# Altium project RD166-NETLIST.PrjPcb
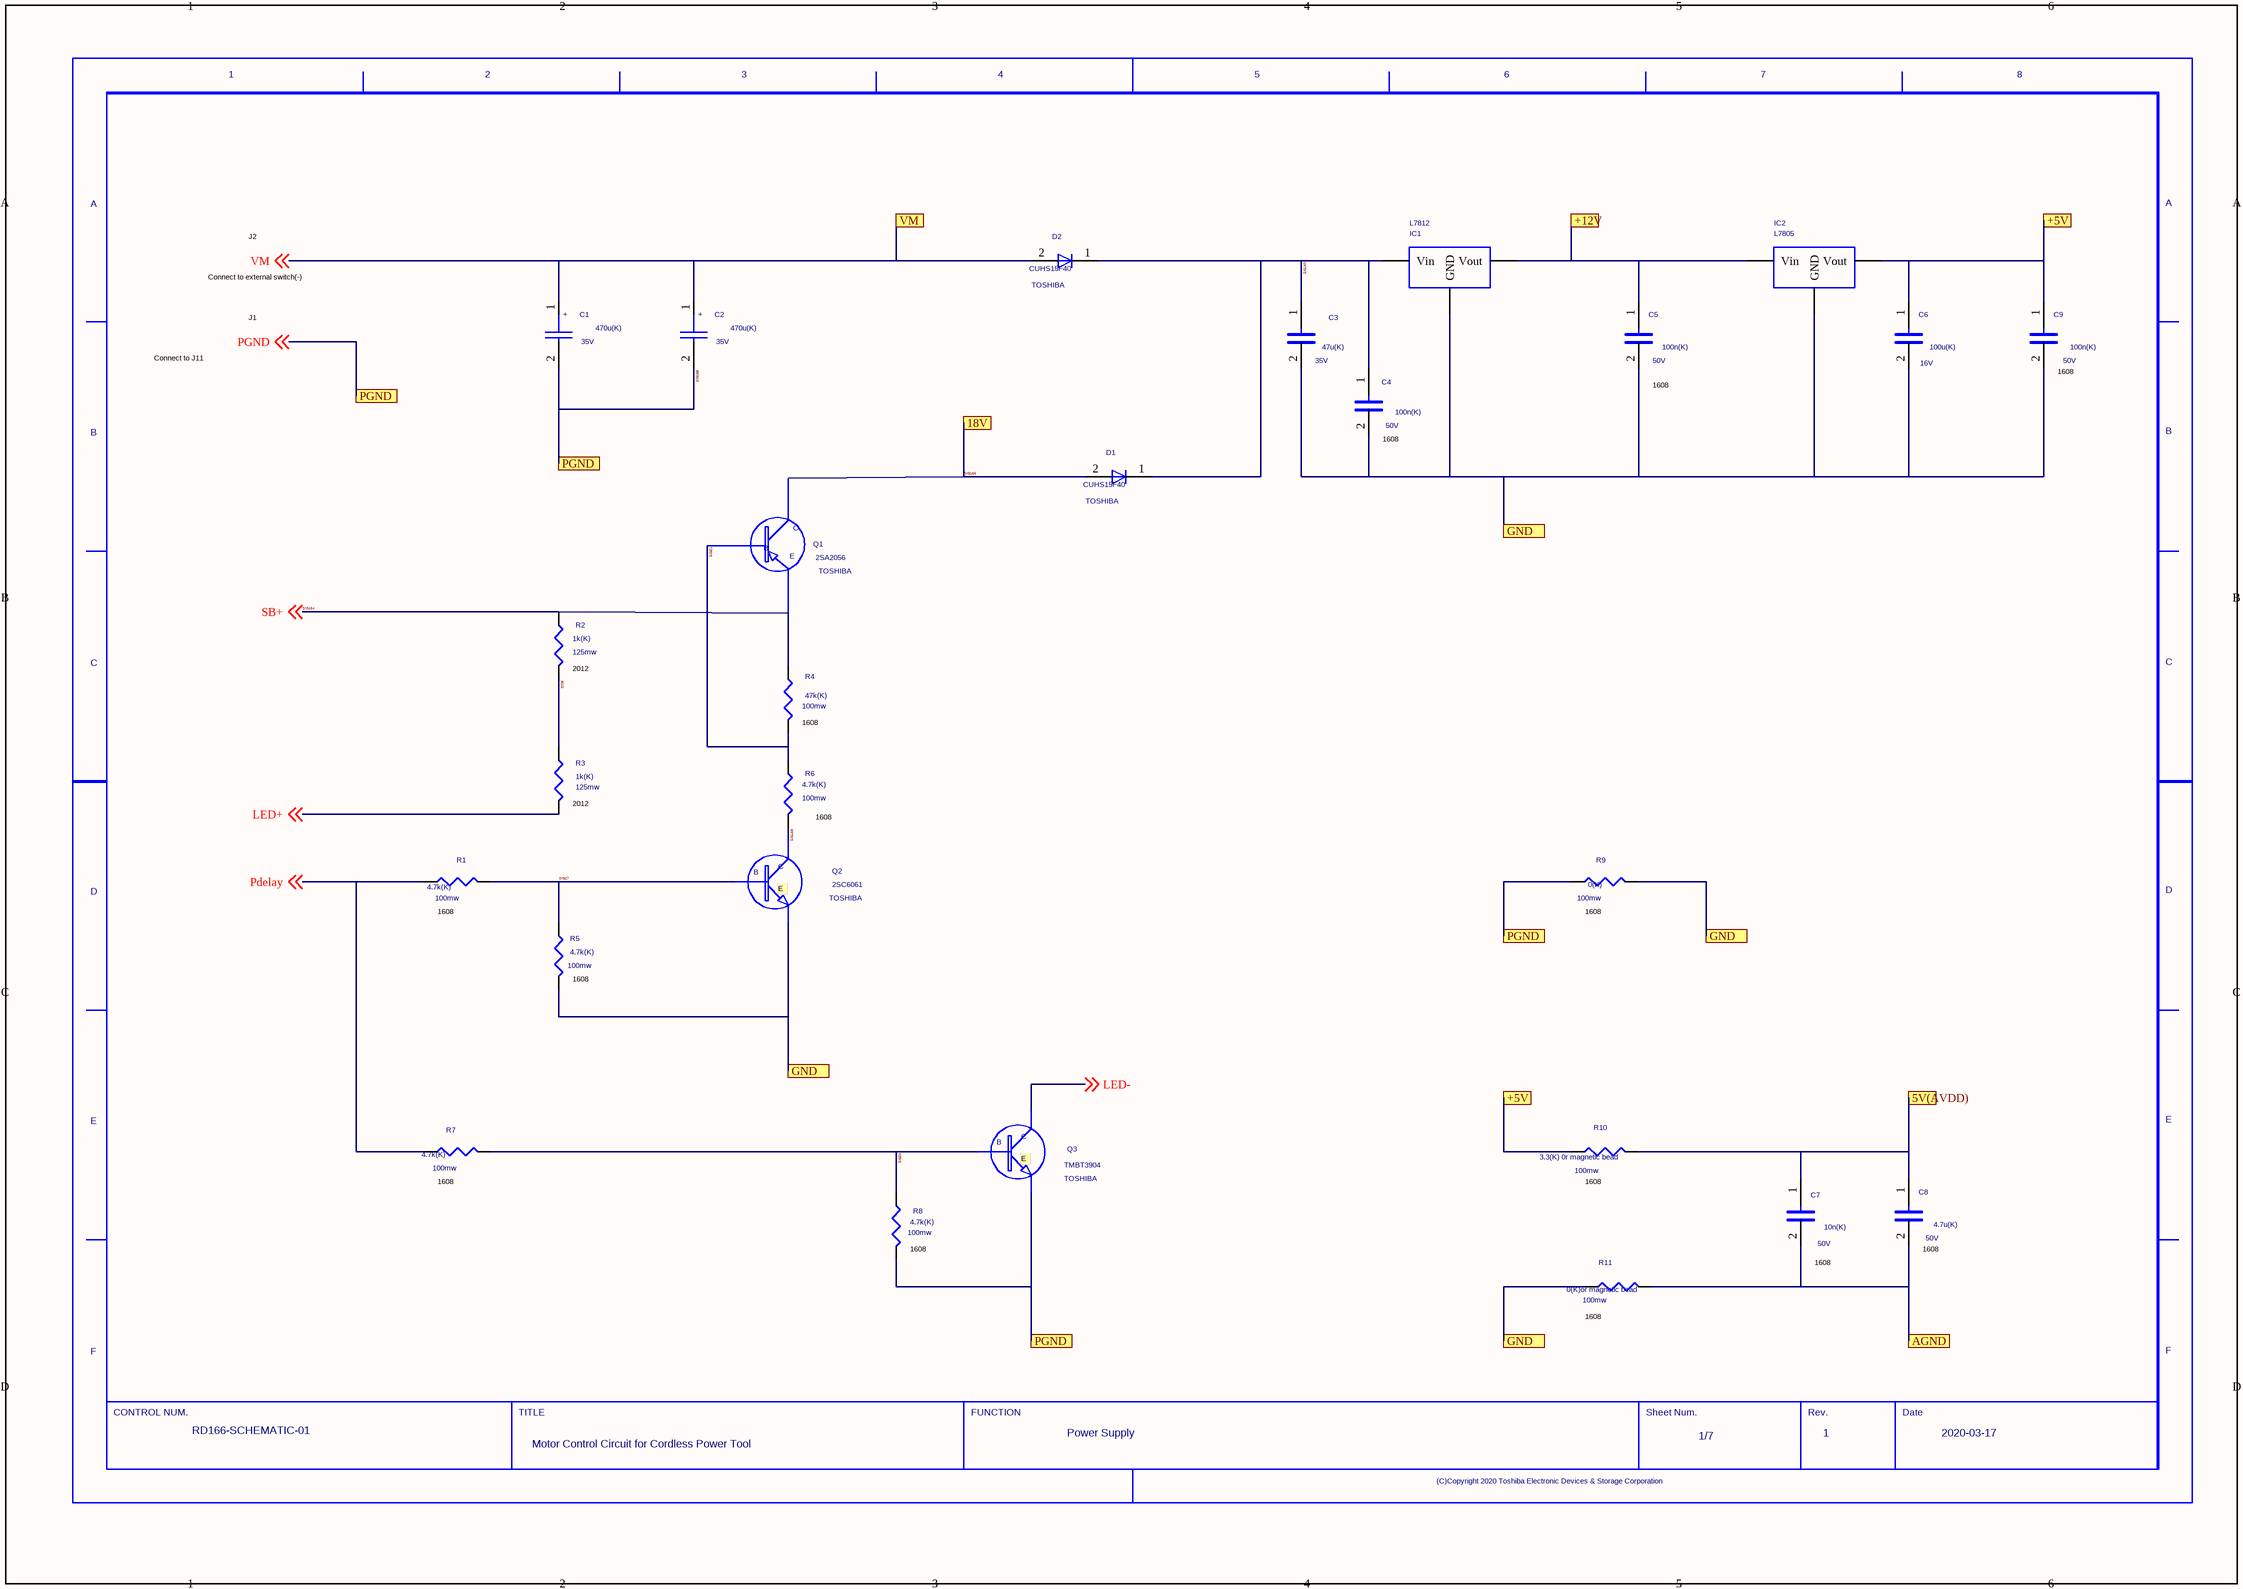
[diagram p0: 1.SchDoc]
7 sheets, 145 parts. Net scope: flat (ports and power ports of the same name join across sheets).
Sheets:
  1.SchDoc
  2.SchDoc
  3.SchDoc
  4.SchDoc
  5.SchDoc
  6.SchDoc
  7.SchDoc

## Sheet 1.SchDoc
size 420 x 297 mm

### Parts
(Parts that share a designator on the sheet are numbered #1, #2 ... from top to bottom, then left to right.)
C1  VAL2: 35V  VAL1: 470u(K)  (hidden comment: CP)
C2  VAL2: 35V  VAL1: 470u(K)  (hidden comment: CP)
C3  VAL2: 35V  VAL1: 47u(K)  (hidden comment: C)
C4  VAL2: 50V  VAL1: 100n(K)  (hidden comment: C)
C5  VAL2: 50V  VAL1: 100n(K)  (hidden comment: C)
C6  VAL2: 16V  VAL1: 100u(K)  (hidden comment: C)
C7  VAL2: 50V  VAL1: 10n(K)  (hidden comment: C)
C8  VAL2: 50V  VAL1: 4.7u(K)  (hidden comment: C)
C9  VAL2: 50V  VAL1: 100n(K)  (hidden comment: C)
D1  USERCOMPTEXT3: TOSHIBA  VAL3: CUHS15F40  (hidden comment: D)
D2  USERCOMPTEXT3: TOSHIBA  VAL3: CUHS15F40  (hidden comment: D)
IC1  VAL3: L7812  (hidden comment: L7805)
IC2  L7805
Q1  USERCOMPTEXT3: TOSHIBA  VAL3: 2SA2056  (hidden comment: PNP_2)
Q2  USERCOMPTEXT3: TOSHIBA  VAL3: 2SC6061  (hidden comment: NPN)
Q3  USERCOMPTEXT3: TOSHIBA  VAL3: TMBT3904  (hidden comment: NPN)
R1  VAL2: 100mw  VAL1: 4.7k(K)  (hidden comment: RES_SMD__2)
R2  VAL2: 125mw  VAL1: 1k(K)  (hidden comment: RES_SMD__2)
R3  VAL2: 125mw  VAL1: 1k(K)  (hidden comment: RES_SMD__2)
R4  VAL2: 100mw  VAL1: 47k(K)  (hidden comment: RES_SMD__2)
R5  VAL2: 100mw  VAL1: 4.7k(K)  (hidden comment: RES_SMD__2)
R6  VAL2: 100mw  VAL1: 4.7k(K)  (hidden comment: RES_SMD__2)
R7  VAL2: 100mw  VAL1: 4.7k(K)  (hidden comment: RES_SMD__2)
R8  VAL2: 100mw  VAL1: 4.7k(K)  (hidden comment: RES_SMD__2)
R9  VAL2: 100mw  VAL1: 0(K)  (hidden comment: RES_SMD__2)
R10  VAL2: 100mw  VAL1: 3.3(K) 0r magnetic bead  (hidden comment: RES_SMD__2)
R11  VAL2: 100mw  VAL1: 0(K)or magnetic bead  (hidden comment: RES_SMD__2)
U?#1  DATE: 2020-03-17  REVISION: 1  SHEETNUMBER: 1/7  FUNCTION: Power Supply  DRAWINGNUMBER: RD166-SCHEMATIC-01  TITLE: Motor Control Circuit for / Cordless Power Tool  (hidden comment: WAKU_DEF100)

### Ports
5V(AVDD), 18V, +5V, +12V, AGND, GND, PGND, VM

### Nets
LED+: R3.2 ; off-sheet LED+
LED-: Q3.3 ; off-sheet LED-
Pdelay: R1.2 R7.1 ; off-sheet Pdelay
SIG8: R2.2 R3.1
SIG21: Q1.1 R4.1 R6.1
SIG24: Q3.1 R7.2 R8.1
SIG27: Q2.1 R1.1 R5.2
SIG29: C3.2 C4.2 C5.2 C6.2 C9.2 IC1.2(GND) IC2.2(GND) Q2.2 R5.1 R9.2 R11.1 ; port GND
SIG42: C6.1 C9.1 IC2.3(Vout) R10.1 ; port +5V
SIG163: C3.1 C4.1 D1.1(C) D2.1(C) IC1.1(Vin)
SIG164: Q1.2 R2.1 R4.2 ; off-sheet SB+  [also labelled SB+]
SIG165: C1.2 C2.2 Q3.2 R8.2 R9.1 ; off-sheet PGND, port PGND  [also labelled PGND]
SIG166: D1.2(A) Q1.3 ; port 18V
SIG169: Q2.3 R6.2
VM: C1.1 C2.1 D2.2(A) ; off-sheet VM, port VM
NetC5_1: C5.1 IC1.3(Vout) IC2.1(Vin) ; port +12V
NetC7_1: C7.1 C8.1 R10.2 ; port 5V(AVDD)
NetC7_2: C7.2 C8.2 R11.2 ; port AGND

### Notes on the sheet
- J2
- Connect to external switch(-)
- J1
- Connect to J11
- (near C5) 1608
- (near C9) 1608
- (near C4) 1608
- (near R2) 2012
- (near R4) 1608
- (near R3) 2012
- 1608
- (near R1) 1608
- (near R9) 1608
- (near R5) 1608
- (near R7) 1608
- (near R10) 1608
- (near R8) 1608
- (near C7) 1608
- (near C8) 1608
- (near R11) 1608

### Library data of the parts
C1 C2 = CP: PARTNAME: 470UF_K; OriginalSymbolOrigin: (2540,10160); UPDATETIME: 16:13:42; UPDATEUSER: fukuda-y; TIME: 15:02:55; SAVECOUNT: 52; SAVEAREA0: -1450,-153,20294,13055
C3 = C: PARTNAME: 47UF_K; OriginalSymbolOrigin: (2540,7620)
C4 C5 C9 = C: PARTNAME: 100NF_K; OriginalSymbolOrigin: (2540,7620)
C6 = C: PARTNAME: 100UF_K; OriginalSymbolOrigin: (2540,7620)
C7 = C: PARTNAME: 10NF_K; OriginalSymbolOrigin: (2540,7620)
C8 = C: PARTNAME: 4-7UF_K; OriginalSymbolOrigin: (2540,7620)
D1 D2 = D: OriginalSymbolOrigin: (5080,5080); UPDATETIME: 14:20:16; UPDATEUSER: 19870035; TIME: 14:49:55; SAVECOUNT: 3; SAVEAREA0: -225,-91,12804,7836
IC1 IC2 = L7805: OriginalSymbolOrigin: (0,0); SAVEAREA0: -9544,-9544,24191,4569; SAVECOUNT: 2; UPDATETIME: 10:58:54; UPDATEUSER: t5459927; TIME: 14:48:25
Q1 = PNP_2: OriginalSymbolOrigin: (-10142,10288); SAVEAREA0: -33169,-19071,44577,13455; SAVECOUNT: 4; UPDATETIME: 08:35:52; UPDATEUSER: t5459927; TIME: 14:48:25
Q2 Q3 = NPN: OriginalSymbolOrigin: (-2537,2540); SAVEAREA0: -26556,-14535,34190,10878; SAVECOUNT: 4; UPDATETIME: 08:38:55; UPDATEUSER: t5459927; TIME: 14:48:25
R1 R5 = RES_SMD__2: PARTNAME: 4-7K_K; OriginalSymbolOrigin: (2552,2560); SAVEAREA0: -3866,-5393,16243,5158; SAVECOUNT: 2; UPDATETIME: 10:20:03; UPDATEUSER: t5459927; TIME: 14:48:25
R2 R3 = RES_SMD__2#1: PARTNAME: 1K_K; OriginalSymbolOrigin: (2552,2560); SAVEAREA0: -3866,-5393,16243,5158; SAVECOUNT: 2; UPDATETIME: 10:20:03; UPDATEUSER: t5459927; TIME: 14:48:25; CaptureCellPackProp: RES_SMD__2##1
R4 = RES_SMD__2: PARTNAME: 47K_K; OriginalSymbolOrigin: (2552,2560); SAVEAREA0: -3866,-5393,16243,5158; SAVECOUNT: 2; UPDATETIME: 10:20:03; UPDATEUSER: t5459927; TIME: 14:48:25
R6-R8 = RES_SMD__2#1: PARTNAME: 4-7K_K; OriginalSymbolOrigin: (2552,2560); SAVEAREA0: -3866,-5393,16243,5158; SAVECOUNT: 2; UPDATETIME: 10:20:03; UPDATEUSER: t5459927; TIME: 14:48:25; CaptureCellPackProp: RES_SMD__2##1
R9 = RES_SMD__2#1: PARTNAME: 0_K; OriginalSymbolOrigin: (2552,2560); SAVEAREA0: -3866,-5393,16243,5158; SAVECOUNT: 2; UPDATETIME: 10:20:03; UPDATEUSER: t5459927; TIME: 14:48:25; CaptureCellPackProp: RES_SMD__2##1
R10 = RES_SMD__2#1: PARTNAME: 3-3_K_OR_MAGNETIC_BEAD; OriginalSymbolOrigin: (2552,2560); SAVEAREA0: -3866,-5393,16243,5158; SAVECOUNT: 2; UPDATETIME: 10:20:03; UPDATEUSER: t5459927; TIME: 14:48:25; CaptureCellPackProp: RES_SMD__2##1
R11 = RES_SMD__2#1: PARTNAME: 0_K_OR_MAGNETIC_BEAD; OriginalSymbolOrigin: (2552,2560); SAVEAREA0: -3866,-5393,16243,5158; SAVECOUNT: 2; UPDATETIME: 10:20:03; UPDATEUSER: t5459927; TIME: 14:48:25; CaptureCellPackProp: RES_SMD__2##1
U?#1 = WAKU_DEF100: OriginalSymbolOrigin: (10160,284480); SAVECOUNT: 4; UPDATETIME: 15:05:57; UPDATEUSER: t5459927; TIME: 14:30:25; SAVEAREA0: 198008,-65938,436964,90161; PLOTTIME: HH:MM

## Sheet 2.SchDoc
size 420 x 297 mm
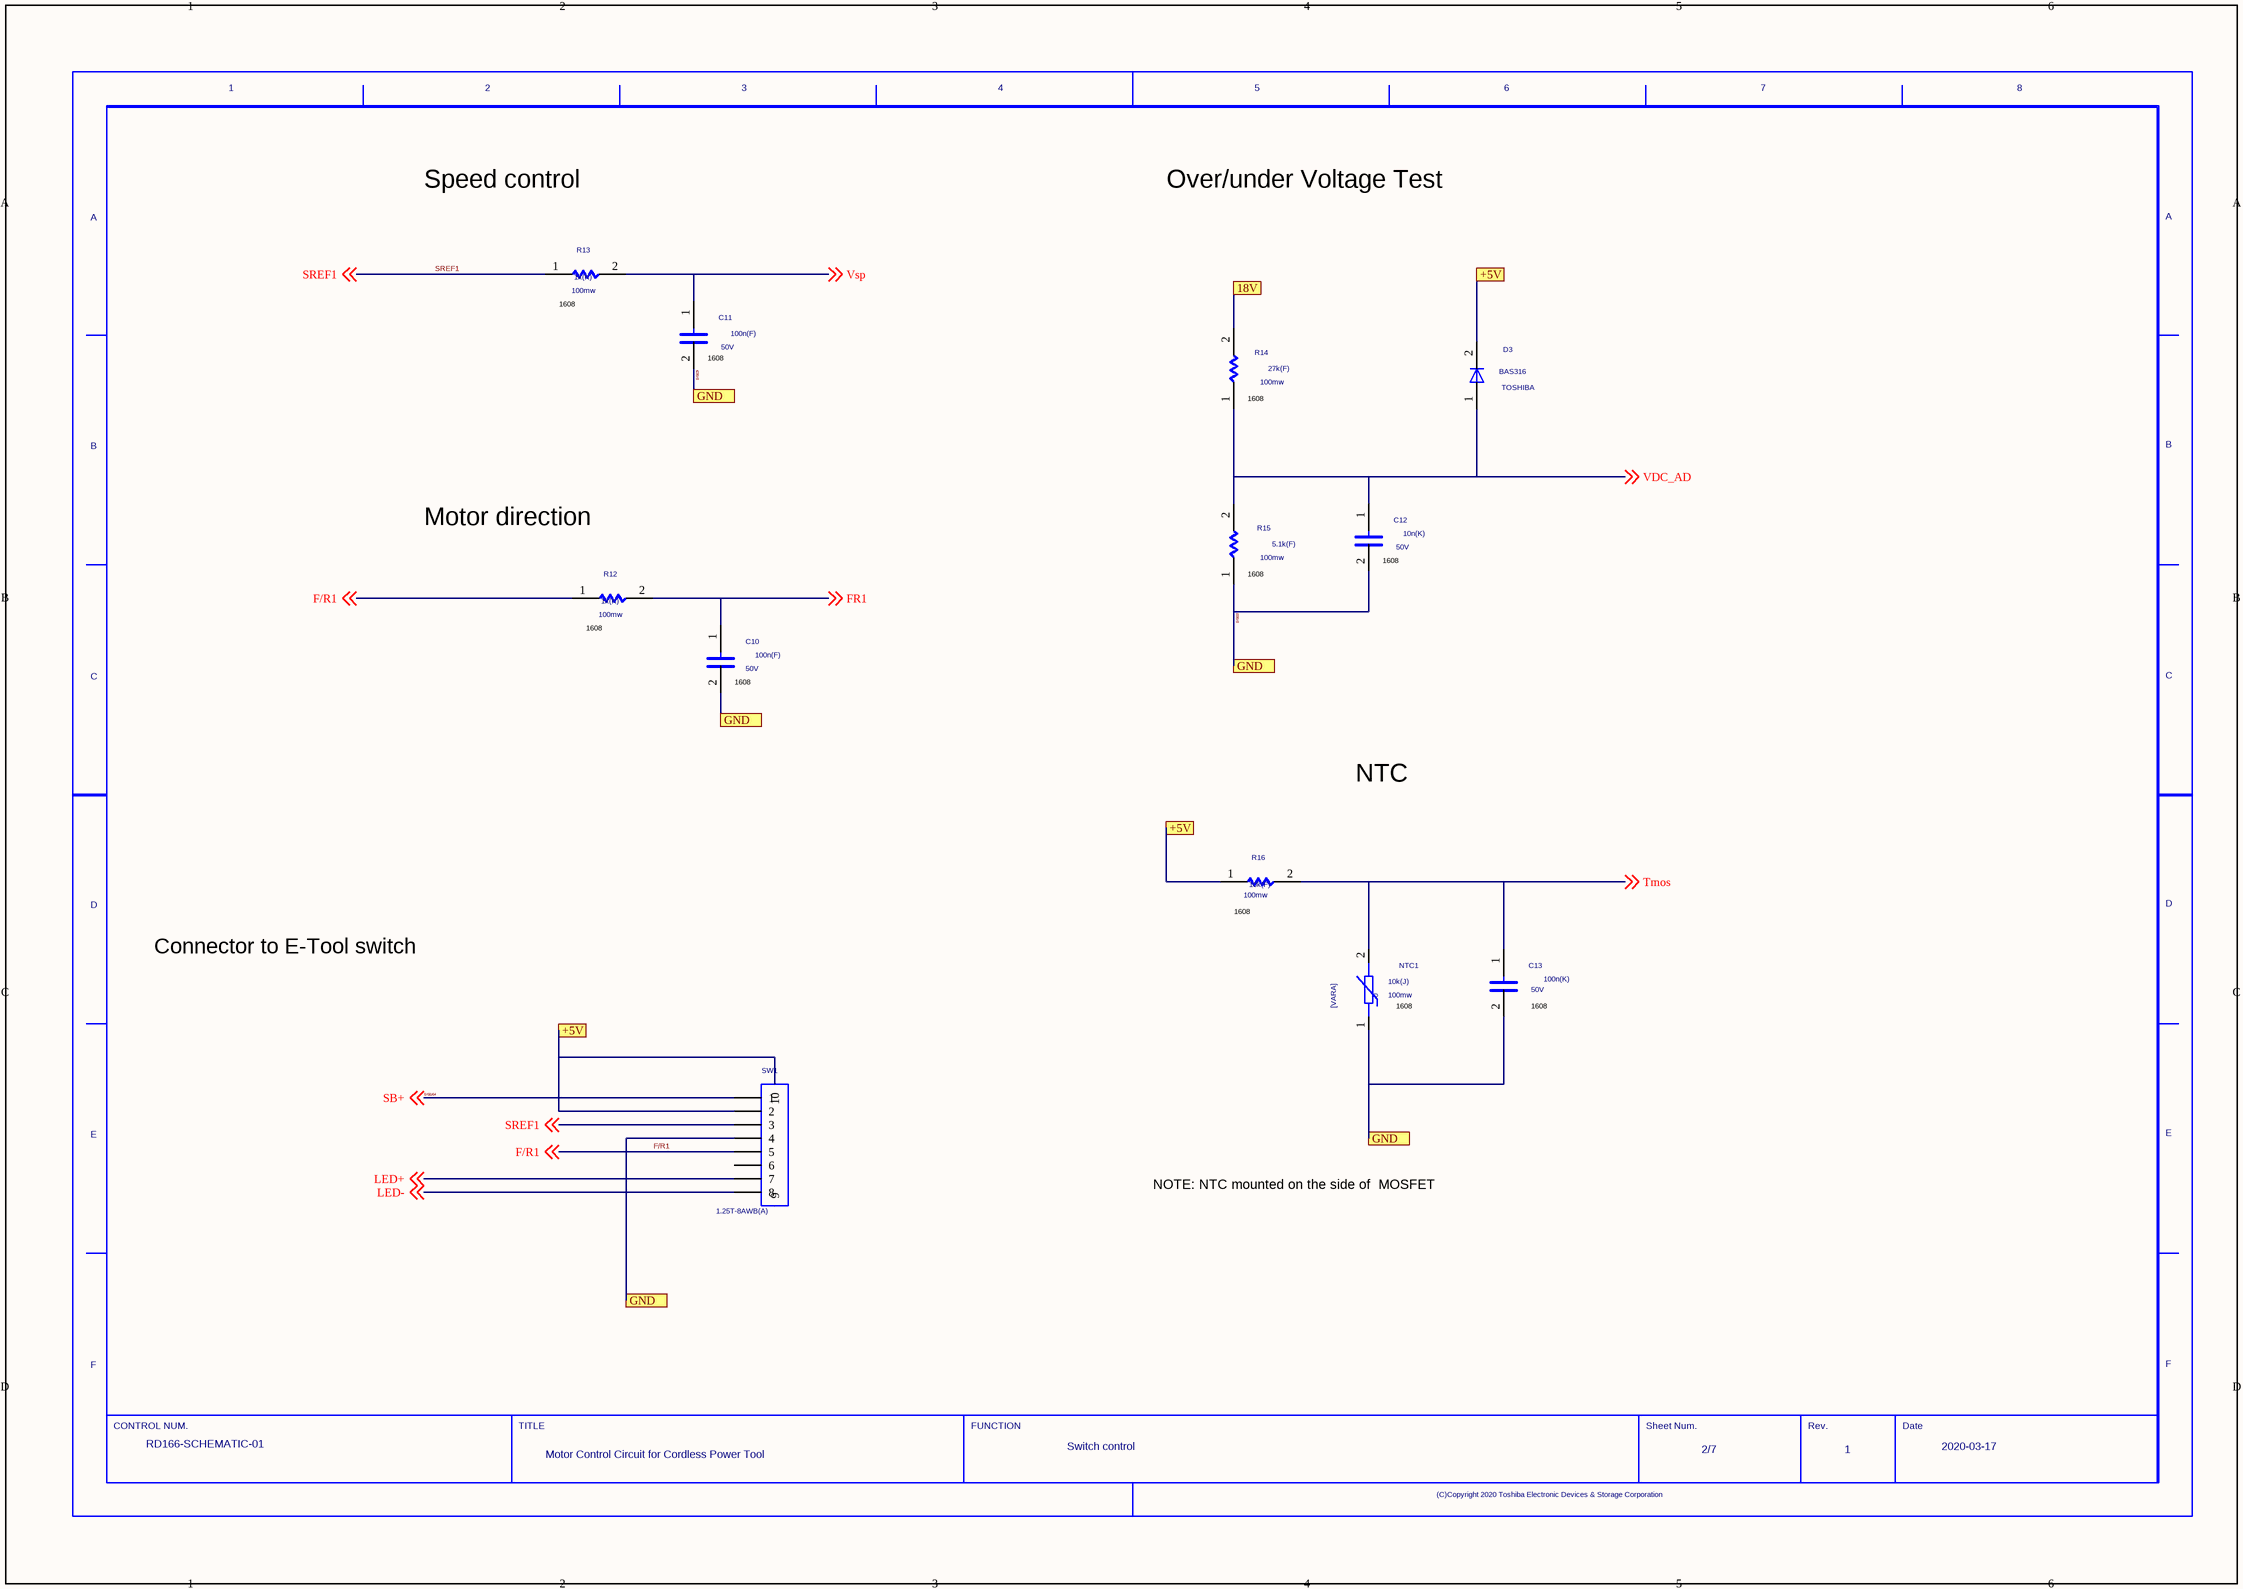
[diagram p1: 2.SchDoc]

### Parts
(Parts that share a designator on the sheet are numbered #1, #2 ... from top to bottom, then left to right.)
C10  VAL2: 50V  VAL1: 100n(F)  (hidden comment: C)
C11  VAL2: 50V  VAL1: 100n(F)  (hidden comment: C)
C12  VAL2: 50V  VAL1: 10n(K)  (hidden comment: C)
C13  VAL2: 50V  VAL1: 100n(K)  (hidden comment: C)
D3  USERCOMPTEXT3: TOSHIBA  VAL3: BAS316  (hidden comment: D)
NTC1  VAL2: 100mw  VAL1: 10k(J)  (hidden comment: VARA)
R12  VAL2: 100mw  VAL1: 1k(K)  (hidden comment: R)
R13  VAL2: 100mw  VAL1: 1k(K)  (hidden comment: R)
R14  VAL2: 100mw  VAL1: 27k(F)  (hidden comment: R)
R15  VAL2: 100mw  VAL1: 5.1k(F)  (hidden comment: R)
R16  VAL2: 100mw  VAL1: 10k(F)  (hidden comment: R)
SW1  VAL3: 1.25T-8AWB(A)  (hidden comment: CON8)
U?#2  DATE: 2020-03-17  REVISION: 1  SHEETNUMBER: 2/7  FUNCTION: Switch control  TITLE: Motor Control Circuit for / Cordless Power Tool  DRAWINGNUMBER: RD166-SCHEMATIC-01  (hidden comment: WAKU_DEF100)

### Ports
18V, +5V, GND

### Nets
F/R1: R12.1 SW1.5 ; off-sheet F/R1
FR1: C10.1 R12.2 ; off-sheet FR1
LED+: SW1.7 ; off-sheet LED+
LED-: SW1.8 ; off-sheet LED-
SIG29: C10.2 C11.2 C12.2 C13.2 NTC1.1 R15.1 SW1.4 ; port GND  [also labelled SIG33]
SIG42: D3.2(C) R16.1 SW1.0(10) SW1.2 ; port +5V
SIG164: SW1.1 ; off-sheet SB+  [also labelled SB+]
SIG166: R14.2 ; port 18V
SREF1: R13.1 SW1.3 ; off-sheet SREF1
Tmos: C13.1 NTC1.2 R16.2 ; off-sheet Tmos
VDC_AD: C12.1 D3.1(A) R14.1 R15.2 ; off-sheet VDC_AD
Vsp: C11.1 R13.2 ; off-sheet Vsp

Not connected (* = marked no-connect by the designer): SW1 6 9

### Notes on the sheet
- Speed control
- Over/under Voltage Test
- (near R13) 1608
- (near C11) 1608
- (near R14) 1608
- Motor direction
- (near R15) 1608
- (near C12) 1608
- (near R12) 1608
- (near C10) 1608
- NTC
- (near R16) 1608
- Connector to E-Tool switch
- (near NTC1) 1608
- (near C13) 1608
- NOTE: NTC mounted on the side of  MOSFET

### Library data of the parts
C10 C11 C13 = C: as C4 on sheet 1
C12 = C: as C7 on sheet 1
D3 = D#1: OriginalSymbolOrigin: (5080,5080); UPDATETIME: 14:20:16; UPDATEUSER: 19870035; TIME: 14:49:55; SAVECOUNT: 3; SAVEAREA0: -225,-91,12804,7836; CaptureCellPackProp: D##1
NTC1 = VARA: PARTNAME: 10K_B3380; OriginalSymbolOrigin: (2540,5080); UPDATETIME: 09:56:50; UPDATEUSER: tomizawa-y; SAVECOUNT: 12; SAVEAREA0: -9950,-8554,25168,13619
R12 R13 = R: PARTNAME: 1K_K; OriginalSymbolOrigin: (5080,5080)
R14 = R#1: PARTNAME: 27K_F; OriginalSymbolOrigin: (5080,5080); CaptureCellPackProp: R##1
R15 = R#1: PARTNAME: 5-1K_F; OriginalSymbolOrigin: (5080,5080); CaptureCellPackProp: R##1
R16 = R: PARTNAME: 10K_F; OriginalSymbolOrigin: (5080,5080)
SW1 = CON8: PARTNAME: 1-25-A; OriginalSymbolOrigin: (0,0); SAVEAREA0: -35474,-32561,34839,4331; SAVECOUNT: 3; UPDATETIME: 16:40:52; UPDATEUSER: t5459927; TIME: 14:48:25
U?#2 = WAKU_DEF100: OriginalSymbolOrigin: (10160,284480); SAVECOUNT: 4; UPDATETIME: 15:06:18; UPDATEUSER: t5459927; TIME: 14:30:25; SAVEAREA0: 198008,-65938,436964,90161; PLOTTIME: HH:MM

## Sheet 3.SchDoc
size 420 x 297 mm
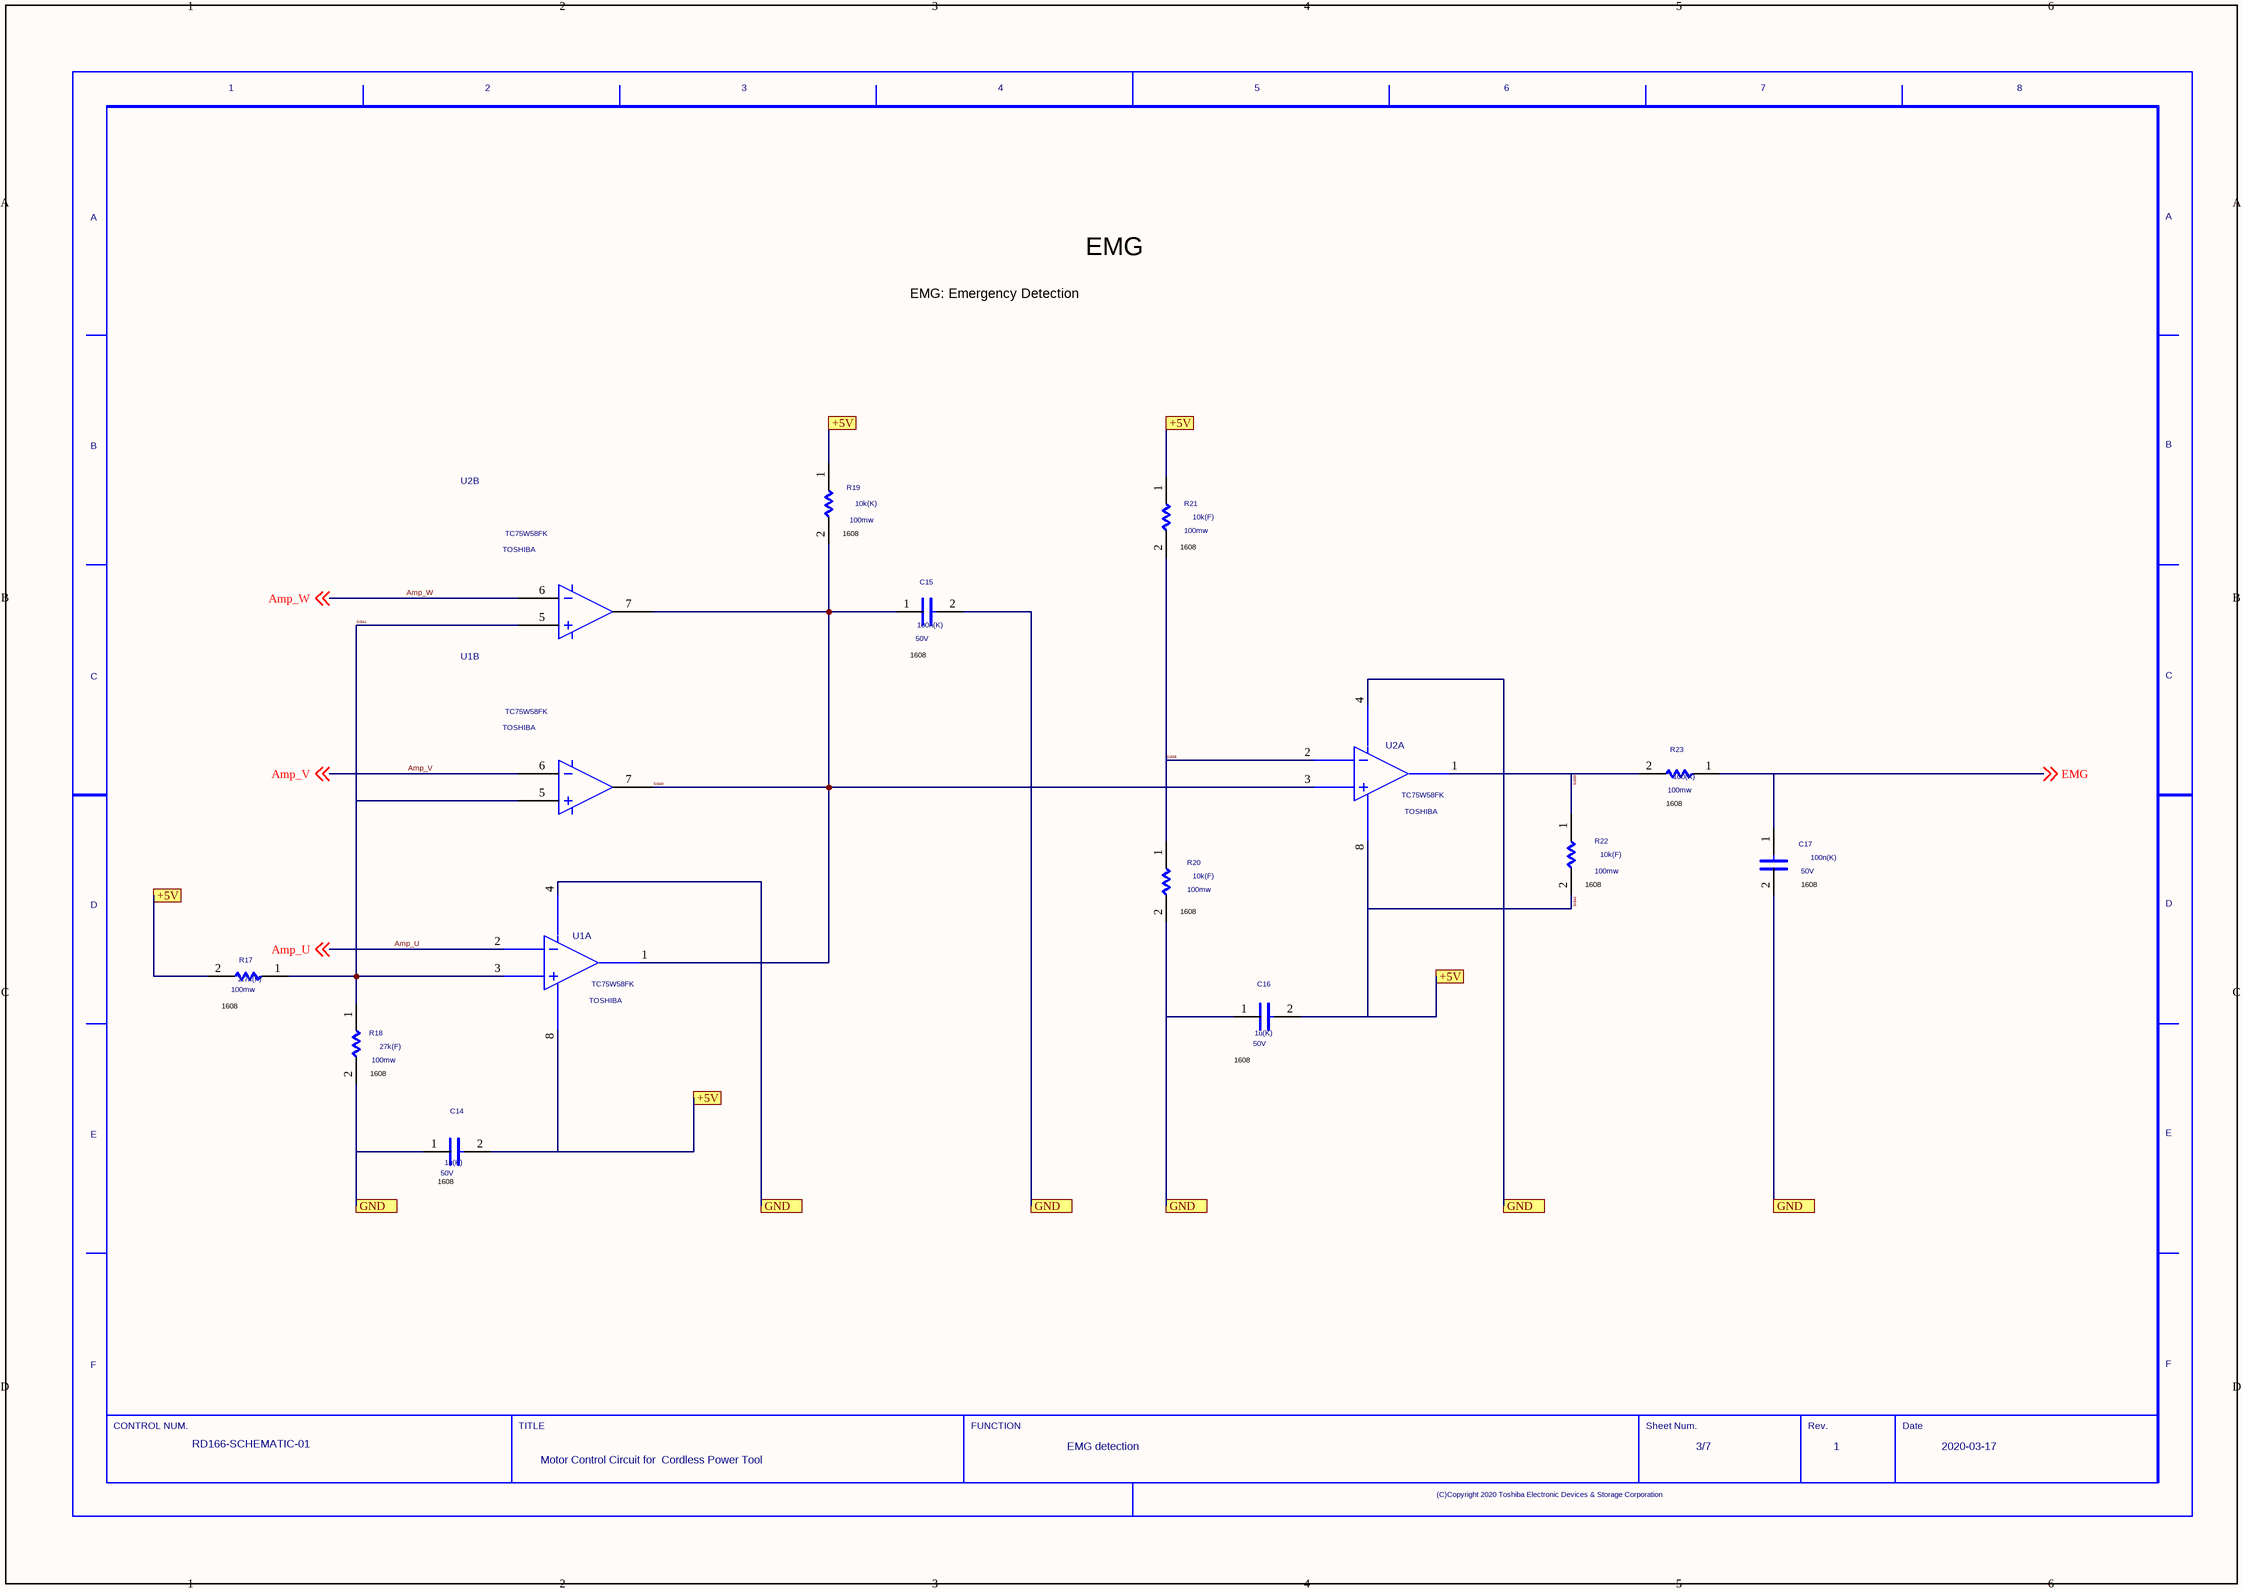
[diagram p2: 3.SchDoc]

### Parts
(Parts that share a designator on the sheet are numbered #1, #2 ... from top to bottom, then left to right.)
C14  VAL2: 50V  VAL1: 1u(K)  (hidden comment: C)
C15  VAL2: 50V  VAL1: 100n(K)  (hidden comment: C)
C16  VAL2: 50V  VAL1: 1u(K)  (hidden comment: C)
C17  VAL2: 50V  VAL1: 100n(K)  (hidden comment: C)
R17  VAL2: 100mw  VAL1: 2.7k(F)  (hidden comment: R)
R18  VAL2: 100mw  VAL1: 27k(F)  (hidden comment: R)
R19  VAL2: 100mw  VAL1: 10k(K)  (hidden comment: R)
R20  VAL2: 100mw  VAL1: 10k(F)  (hidden comment: R)
R21  VAL2: 100mw  VAL1: 10k(F)  (hidden comment: R)
R22  VAL2: 100mw  VAL1: 10k(F)  (hidden comment: R)
R23  VAL2: 100mw  VAL1: 100(K)  (hidden comment: R)
U1  USERCOMPTEXT3: TOSHIBA  [SSOP8-0_5]  (hidden comment: TC75W58FK)  (parts A,B of 2)
U2  USERCOMPTEXT3: TOSHIBA  [SSOP8-0_5]  (hidden comment: TC75W58FK)  (parts A,B of 2)
U?#3  DATE: 2020-03-17  REVISION: 1  SHEETNUMBER: 3/7  FUNCTION: EMG detection  TITLE: Motor Control Circuit for / Cordless Power Tool  DRAWINGNUMBER: RD166-SCHEMATIC-01  (hidden comment: WAKU_DEF100)

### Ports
+5V, GND

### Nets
Amp_U: U1.2 ; off-sheet Amp_U
Amp_V: U1.6 ; off-sheet Amp_V
Amp_W: U2.6 ; off-sheet Amp_W
EMG: C17.1 R23.1 ; off-sheet EMG
SIG29: C14.1 C15.2 C16.1 C17.2 R18.2 R20.2 U1.4 U2.4 ; port GND
SIG38: R20.1 R21.2 U2.2
SIG39: R22.1 R23.2 U2.1
SIG40: C15.1 R19.2 U1.1 U1.7 U2.3 U2.7
SIG41: R17.1 R18.1 U1.3 U1.5 U2.5
SIG42: C14.2 C16.2 R17.2 R19.1 R21.1 R22.2 U1.8 U2.8 ; port +5V

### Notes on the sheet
- EMG
- EMG: Emergency Detection
- (near R19) 1608
- (near R21) 1608
- (near C15) 1608
- (near R23) 1608
- (near R20) 1608
- (near R22) 1608
- (near C17) 1608
- (near R17) 1608
- (near C16) 1608
- (near R18) 1608
- (near C14) 1608

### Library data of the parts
C14 C16 = C#1: PARTNAME: 1UF_K; OriginalSymbolOrigin: (2540,7620); CaptureCellPackProp: C##1
C15 = C#1: PARTNAME: 100NF_K; OriginalSymbolOrigin: (2540,7620); CaptureCellPackProp: C##1
C17 = C: as C4 on sheet 1
R17 = R#1: PARTNAME: 2-7K_F; OriginalSymbolOrigin: (5080,5080); CaptureCellPackProp: R##1
R18 = R: PARTNAME: 27K_F; OriginalSymbolOrigin: (5080,5080)
R19 = R: PARTNAME: 10K_K; OriginalSymbolOrigin: (5080,5080)
R20-R22 = R: as R16 on sheet 2
R23 = R#1: PARTNAME: 100_K; OriginalSymbolOrigin: (5080,5080); CaptureCellPackProp: R##1
U1 = LM193_1B: OriginalSymbolOrigin: (0,0); SAVECOUNT: 1; UPDATETIME: 14:48:25; UPDATEUSER: d5009410; CaptureCellPackProp: LM193_1BA; INSTANCENAME: INS256737
U2 = LM193_1B: OriginalSymbolOrigin: (0,0); SAVECOUNT: 1; UPDATETIME: 14:48:25; UPDATEUSER: d5009410; CaptureCellPackProp: LM193_1BA; INSTANCENAME: INS256705
U?#3 = WAKU_DEF100: OriginalSymbolOrigin: (10160,284480); SAVECOUNT: 4; UPDATETIME: 15:06:36; UPDATEUSER: t5459927; TIME: 14:30:25; SAVEAREA0: 198008,-65938,436964,90161; PLOTTIME: HH:MM

## Sheet 4.SchDoc
size 420 x 297 mm
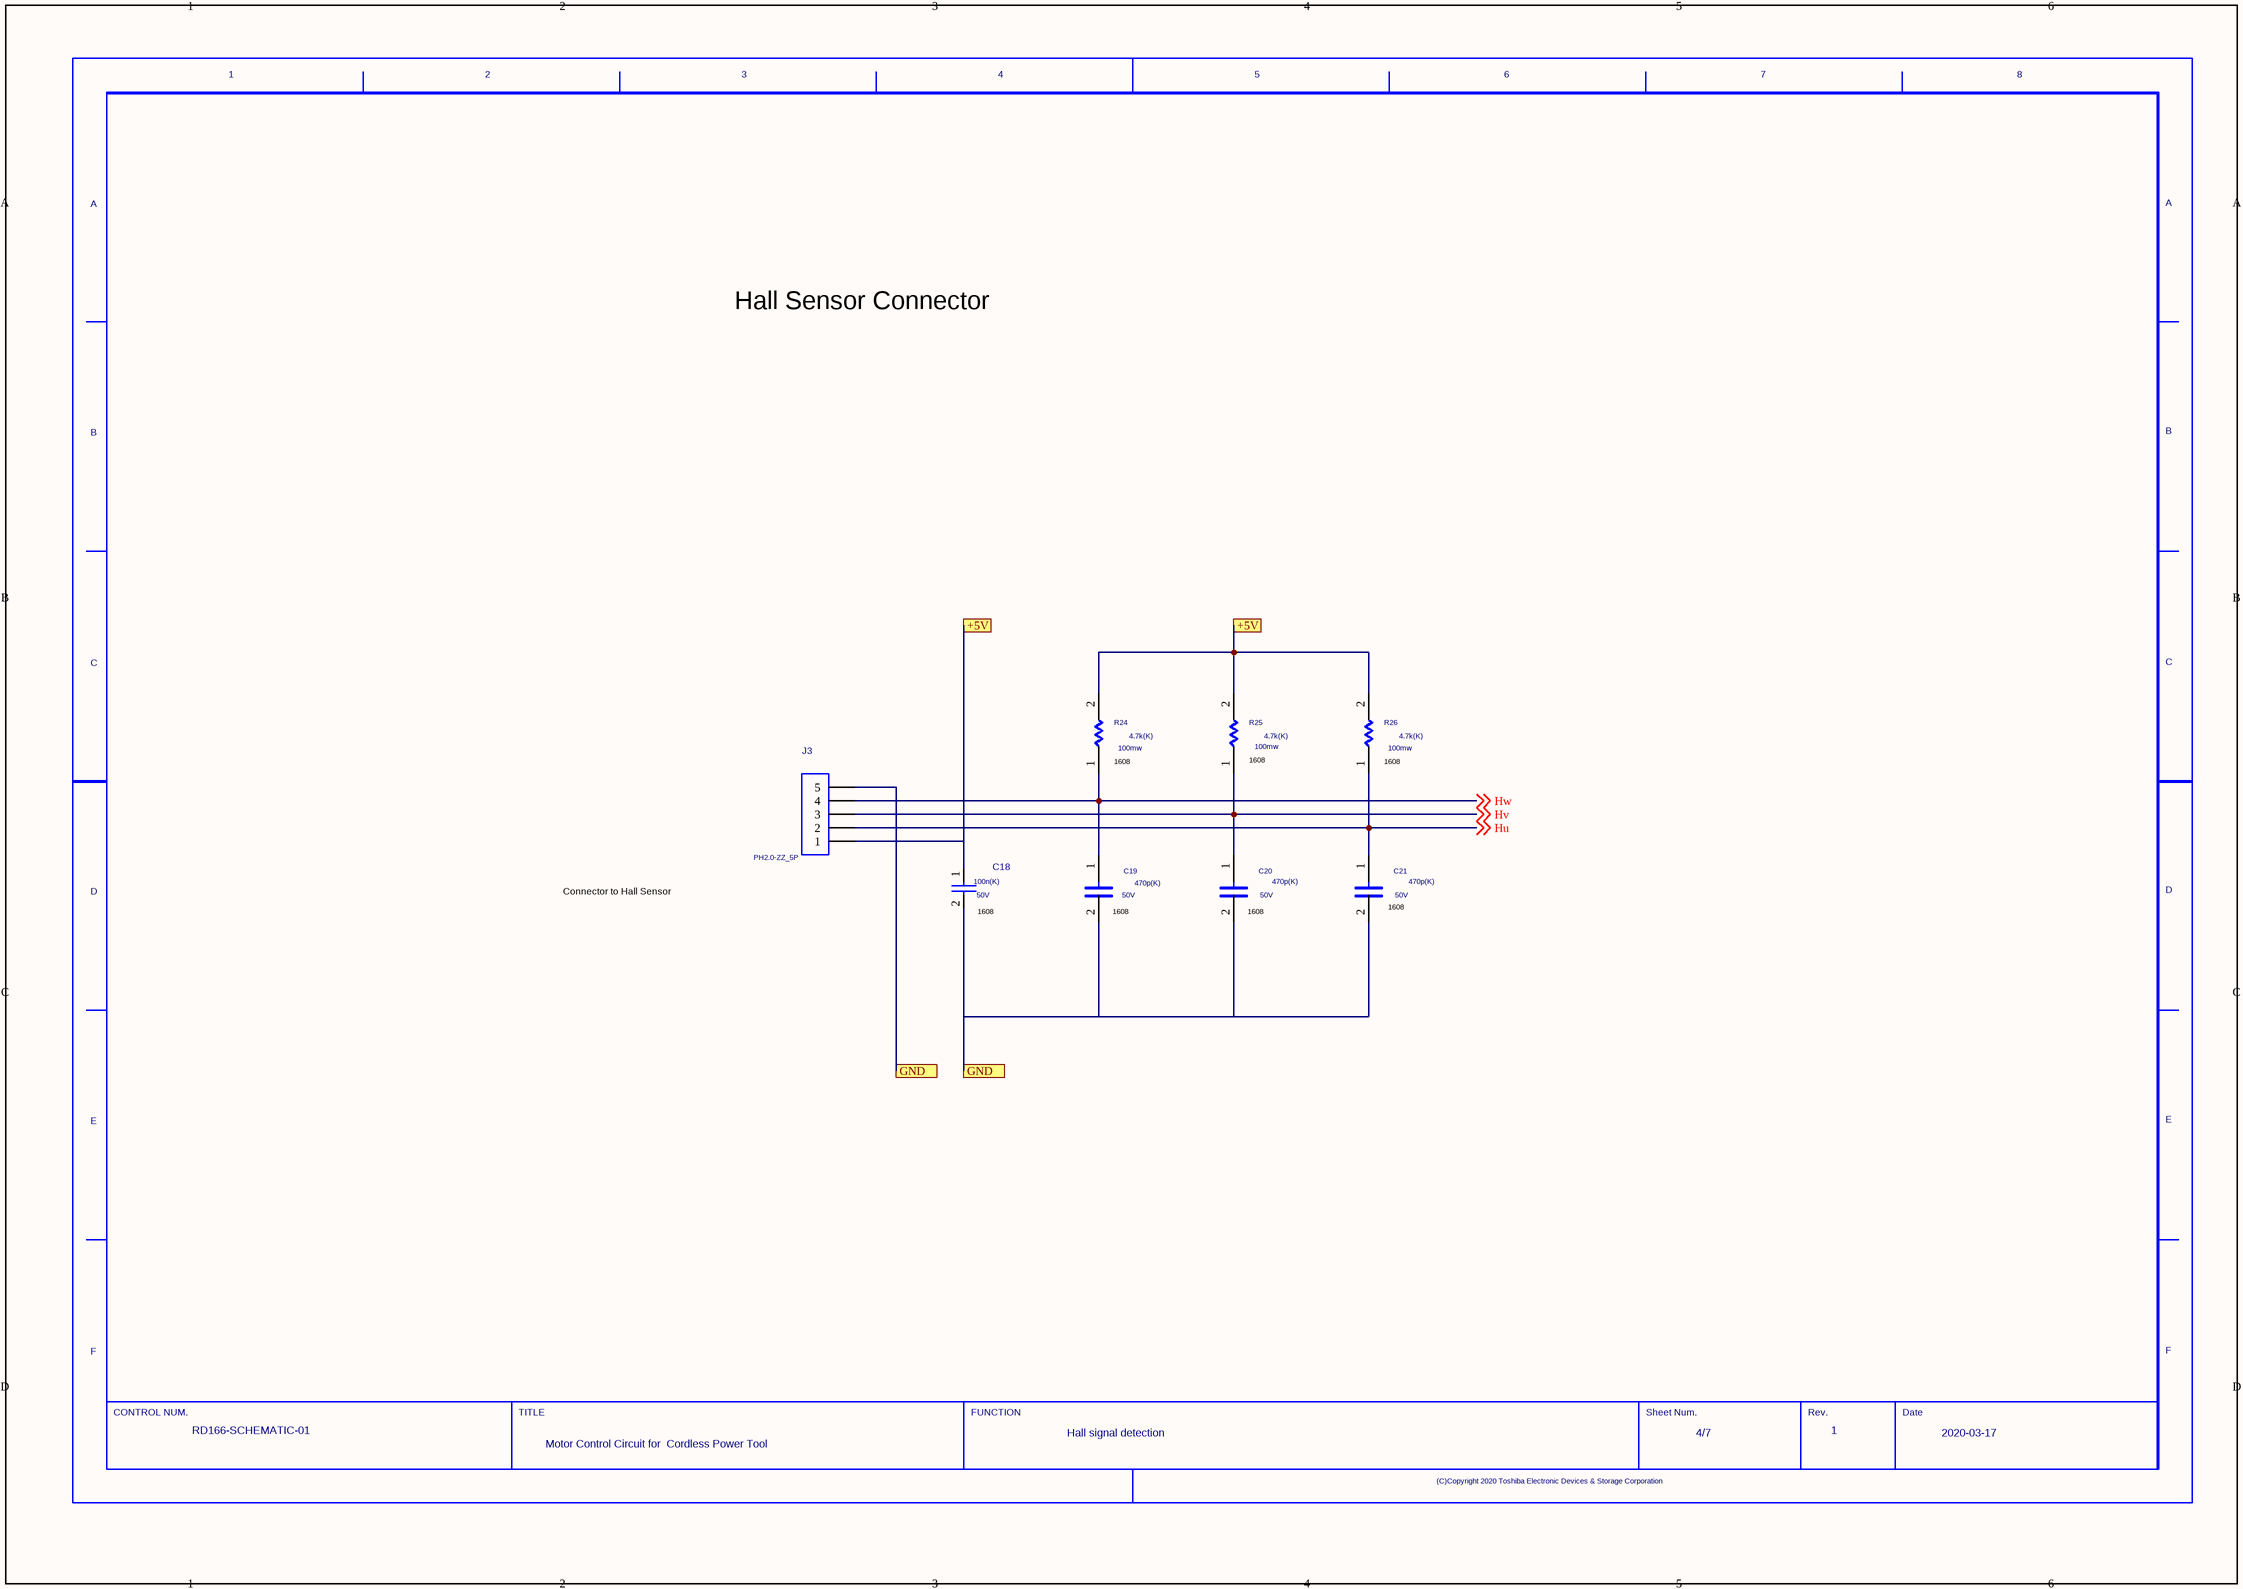
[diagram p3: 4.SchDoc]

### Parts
(Parts that share a designator on the sheet are numbered #1, #2 ... from top to bottom, then left to right.)
C18  VAL2: 50V  VAL1: 100n(K)  [0603-1]  (hidden comment: 100NF_K)
C19  VAL2: 50V  VAL1: 470p(K)  (hidden comment: C)
C20  VAL2: 50V  VAL1: 470p(K)  (hidden comment: C)
C21  VAL2: 50V  VAL1: 470p(K)  (hidden comment: C)
J3  VAL3: PH2.0-ZZ_5P  [ssip5-4]  (hidden comment: 5P_2-0MM)
R24  VAL2: 100mw  VAL1: 4.7k(K)  (hidden comment: R)
R25  VAL2: 100mw  VAL1: 4.7k(K)  (hidden comment: R)
R26  VAL2: 100mw  VAL1: 4.7k(K)  (hidden comment: R)
U?#4  DATE: 2020-03-17  REVISION: 1  SHEETNUMBER: 4/7  FUNCTION: Hall signal detection  TITLE: Motor Control Circuit for / Cordless Power Tool  DRAWINGNUMBER: RD166-SCHEMATIC-01  (hidden comment: WAKU_DEF100)

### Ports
+5V, GND

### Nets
Hu: C21.1 J3.2 R26.1 ; off-sheet Hu
Hv: C20.1 J3.3 R25.1 ; off-sheet Hv
Hw: C19.1 J3.4 R24.1 ; off-sheet Hw
SIG29: C18.2 C19.2 C20.2 C21.2 J3.5 ; port GND
SIG42: C18.1 J3.1 R24.2 R25.2 R26.2 ; port +5V

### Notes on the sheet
- Hall Sensor Connector
- (near R24) 1608
- (near R25) 1608
- (near R26) 1608
- Connector to Hall Sensor
- (near C18) 1608
- (near C19) 1608
- (near C20) 1608
- (near C21) 1608

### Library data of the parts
C18 = CAP_CC_1: OriginalSymbolOrigin: (0,0); SAVECOUNT: 1; UPDATETIME: 14:48:25; UPDATEUSER: d5009410; INSTANCENAME: INS256977
C19-C21 = C: PARTNAME: 470PF_K; OriginalSymbolOrigin: (2540,7620)
J3 = CON5_180: OriginalSymbolOrigin: (0,0); SAVEAREA0: -6362,-15544,16003,852; SAVECOUNT: 1; UPDATETIME: 14:48:25; UPDATEUSER: d5009410; INSTANCENAME: INS256961
R24-R26 = R#1: PARTNAME: 4-7K_K; OriginalSymbolOrigin: (5080,5080); CaptureCellPackProp: R##1
U?#4 = WAKU_DEF100: OriginalSymbolOrigin: (10160,284480); SAVECOUNT: 4; UPDATETIME: 15:06:58; UPDATEUSER: t5459927; TIME: 14:30:25; SAVEAREA0: 198008,-65938,436964,90161; PLOTTIME: HH:MM

## Sheet 5.SchDoc
size 420 x 297 mm
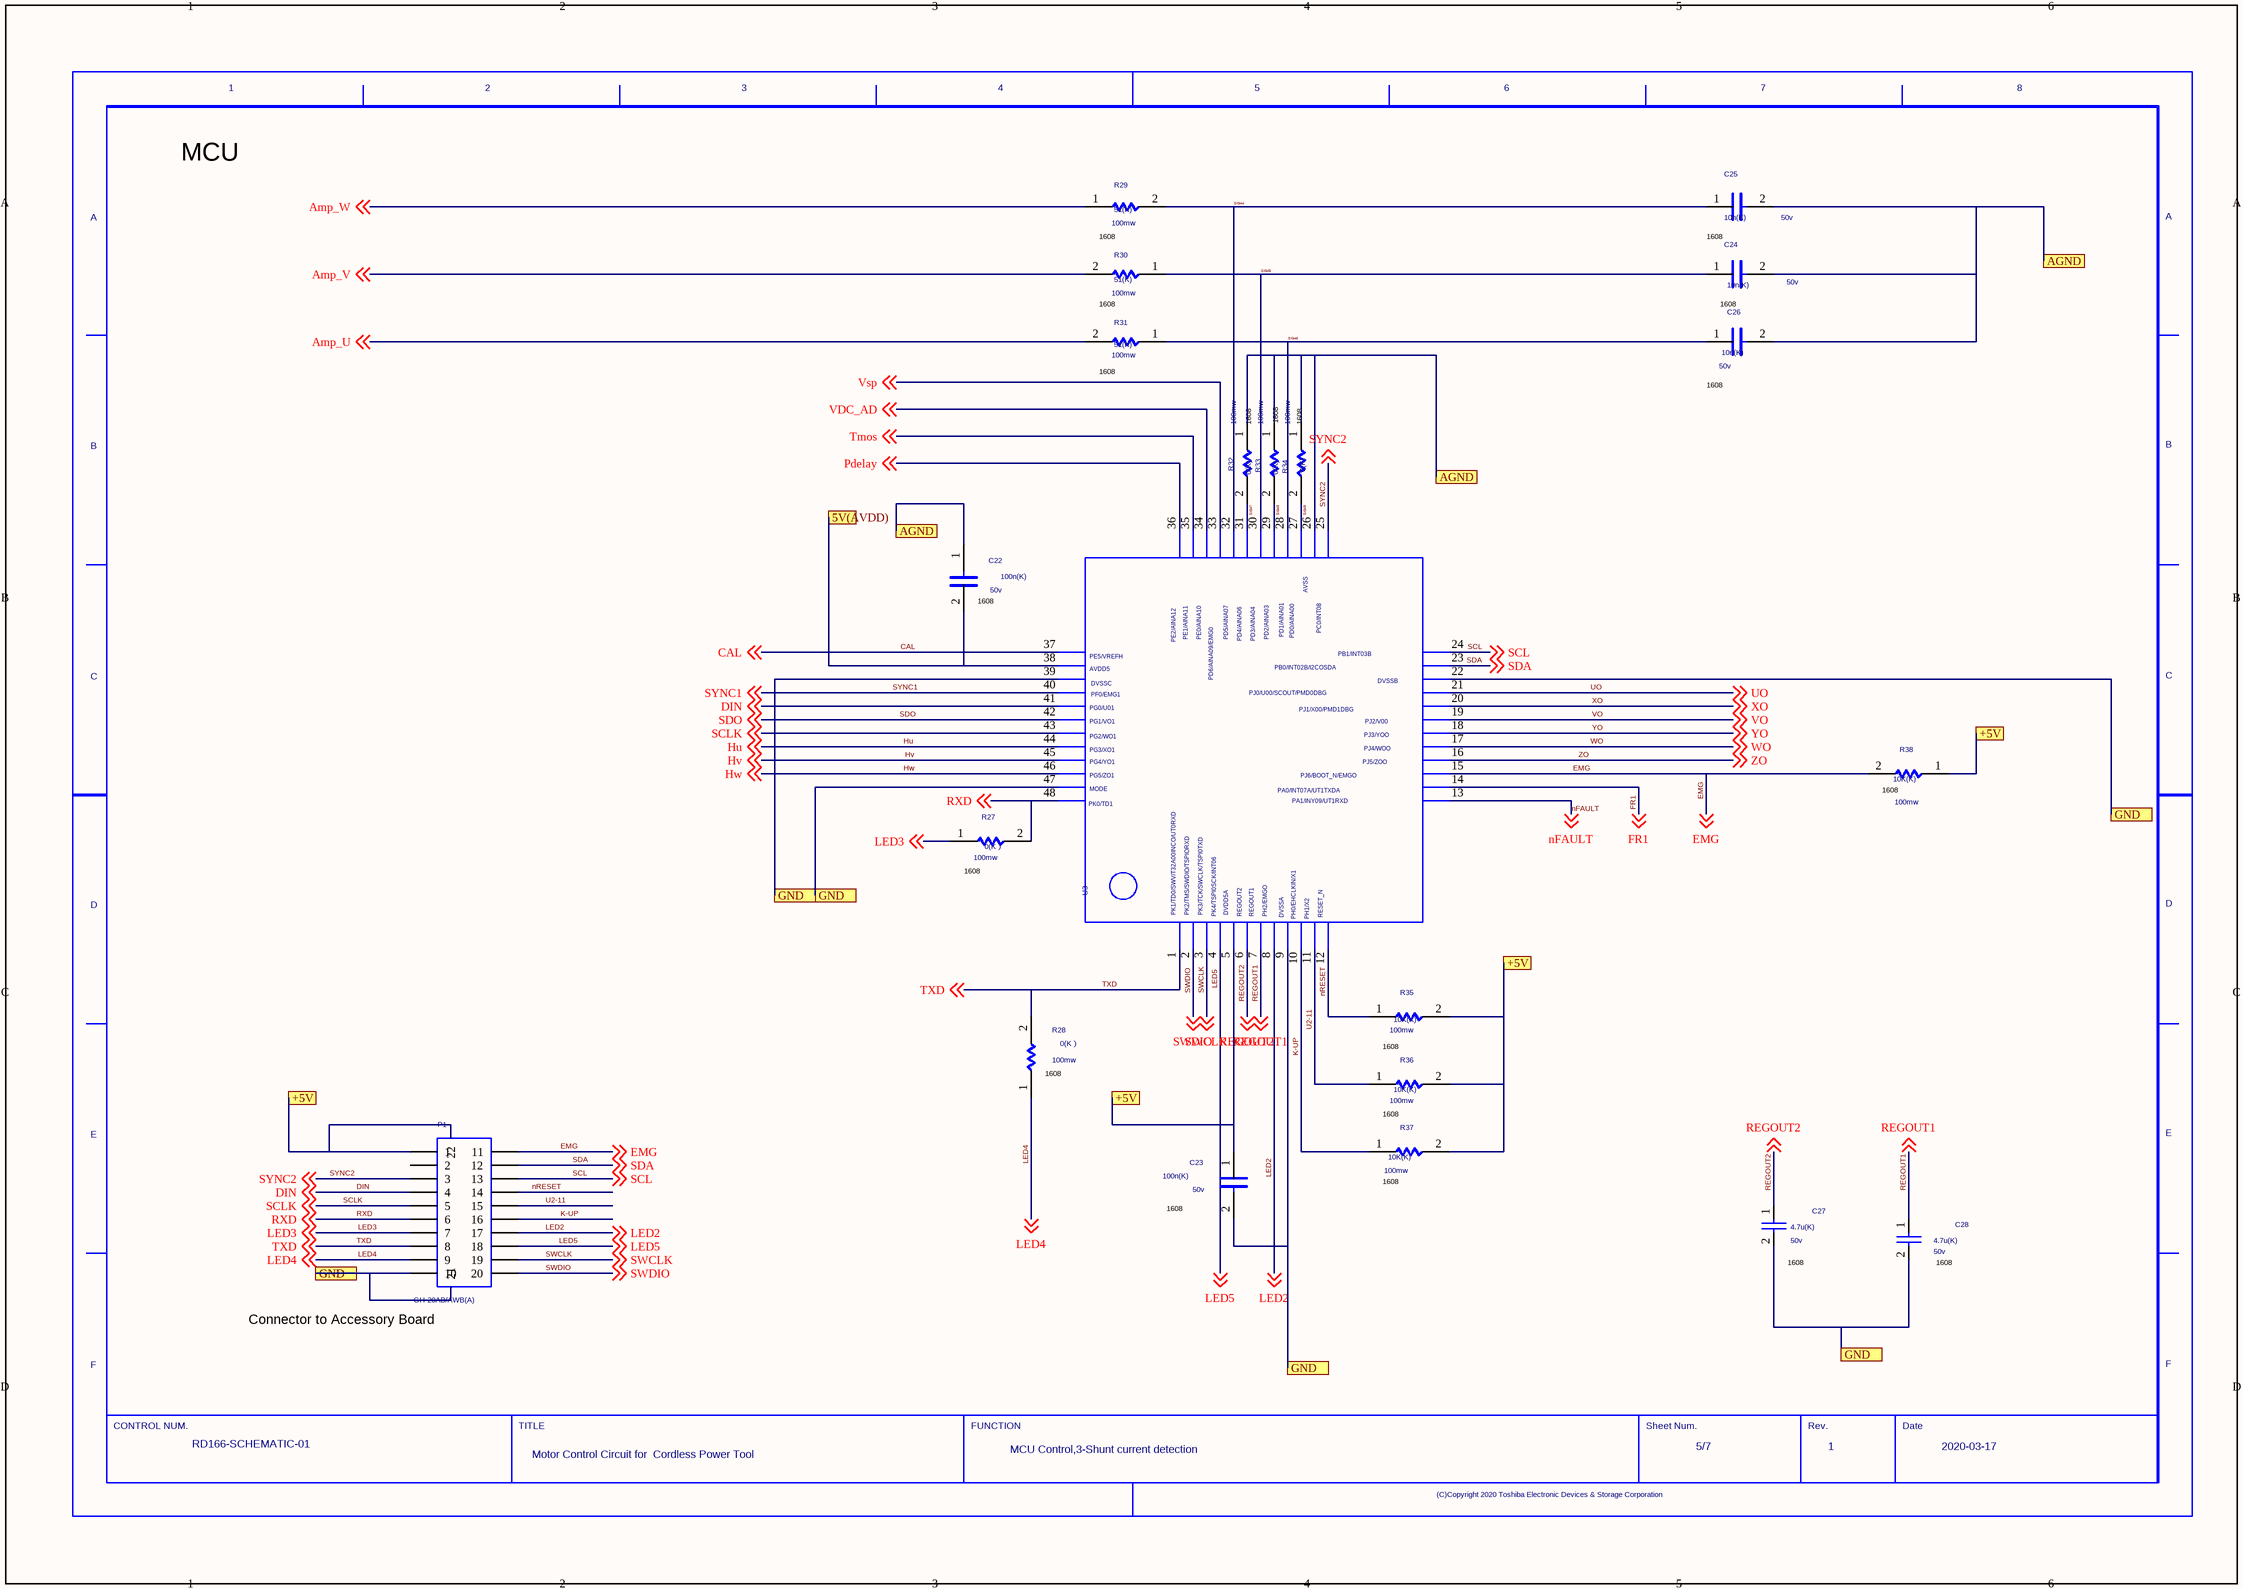
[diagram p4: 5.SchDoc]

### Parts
(Parts that share a designator on the sheet are numbered #1, #2 ... from top to bottom, then left to right.)
C22  VAL1: 100n(K)  VAL2: 50v  (hidden comment: C)
C23  VAL1: 100n(K)  VAL2: 50v  (hidden comment: C)
C24  VAL1: 10n(K)  VAL2: 50v  (hidden comment: C)
C25  VAL1: 10n(K)  VAL2: 50v  (hidden comment: C)
C26  VAL1: 10n(K)  VAL2: 50v  (hidden comment: C)
C27  VAL1: 4.7u(K)  VAL2: 50v  [0603-1]  (hidden comment: 4-7UF_K)
C28  VAL1: 4.7u(K)  VAL2: 50v  [0603-1]  (hidden comment: 4-7UF_K)
P1  VAL3: GH-20AB/AWB(A)  (hidden comment: HEADER_10X2A)
R27  VAL1: 0(K）  VAL2: 100mw  (hidden comment: R)
R28  VAL1: 0(K）  VAL2: 100mw  (hidden comment: R)
R29  VAL1: 51(K)  VAL2: 100mw  (hidden comment: R)
R30  VAL1: 51(K)  VAL2: 100mw  (hidden comment: R)
R31  VAL1: 51(K)  VAL2: 100mw  (hidden comment: R)
R32  VAL1: 0(K)  VAL2: 100mw  (hidden comment: R)
R33  VAL1: 0(K)  VAL2: 100mw  (hidden comment: R)
R34  VAL1: 0(K)  VAL2: 100mw  (hidden comment: R)
R35  VAL1: 10K(K)  VAL2: 100mw  (hidden comment: R)
R36  VAL1: 10K(K)  VAL2: 100mw  (hidden comment: R)
R37  VAL1: 10K(K)  VAL2: 100mw  (hidden comment: R)
R38  VAL1: 10K(K)  VAL2: 100mw  (hidden comment: R)
U3  ETOOLMICON  (value not drawn)
U?#5  DATE: 2020-03-17  DRAWINGNUMBER: RD166-SCHEMATIC-01  TITLE: Motor Control Circuit for / Cordless Power Tool  FUNCTION: MCU Control,3-Shunt current detection  SHEETNUMBER: 5/7  REVISION: 1  (hidden comment: WAKU_DEF100)

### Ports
5V(AVDD), +5V, AGND, GND

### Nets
Amp_U: R31.2 ; off-sheet Amp_U
Amp_V: R30.2 ; off-sheet Amp_V
Amp_W: R29.1 ; off-sheet Amp_W
CAL: U3.37 ; off-sheet CAL
DIN: P1.4 U3.41 ; off-sheet DIN
EMG: P1.11 R38.2 U3.15 ; off-sheet EMG
FR1: U3.14 ; off-sheet FR1
Hu: U3.44 ; off-sheet Hu
Hv: U3.45 ; off-sheet Hv
Hw: U3.46 ; off-sheet Hw
K-UP: P1.16 R37.1 U3.10
LED2: P1.17 U3.8 ; off-sheet LED2
LED3: P1.7 R27.1 ; off-sheet LED3
LED4: P1.9 R28.1 ; off-sheet LED4
LED5: P1.18 U3.4 ; off-sheet LED5
nFAULT: U3.13 ; off-sheet nFAULT
nRESET: P1.14 R35.1 U3.12
Pdelay: U3.36 ; off-sheet Pdelay
REGOUT1: C28.1 U3.7 ; off-sheet REGOUT1
REGOUT2: C27.1 U3.6 ; off-sheet REGOUT2
RXD: P1.6 R27.2 U3.48 ; off-sheet RXD
SCL: P1.13 U3.24 ; off-sheet SCL
SCLK: P1.5 U3.43 ; off-sheet SCLK
SDA: P1.12 U3.23 ; off-sheet SDA
SDO: U3.42 ; off-sheet SDO
SIG29: C23.2 C27.2 C28.2 P1.10 P1.21 U3.9 U3.22 U3.39 U3.47 ; port GND
SIG42: C23.1 P1.1 P1.22 R35.2 R36.2 R37.2 R38.1 U3.5 ; port +5V
SIG44: C25.1 R29.2 U3.32
SIG45: C24.1 R30.1 U3.30
SIG46: C26.1 R31.1 U3.28
SIG47: R32.2 U3.31
SIG48: R33.2 U3.29
SIG49: R34.2 U3.27
SWCLK: P1.19 U3.3 ; off-sheet SWCLK
SWDIO: P1.20 U3.2 ; off-sheet SWDIO
SYNC1: U3.40 ; off-sheet SYNC1
SYNC2: P1.3 U3.25 ; off-sheet SYNC2
Tmos: U3.35 ; off-sheet Tmos
TXD: P1.8 R28.2 U3.1 ; off-sheet TXD
U2-11: P1.15 R36.1 U3.11
UO: U3.21 ; off-sheet UO
VDC_AD: U3.34 ; off-sheet VDC_AD
VO: U3.19 ; off-sheet VO
Vsp: U3.33 ; off-sheet Vsp
WO: U3.17 ; off-sheet WO
XO: U3.20 ; off-sheet XO
YO: U3.18 ; off-sheet YO
ZO: U3.16 ; off-sheet ZO
NetC7_1: C22.2 U3.38 ; port 5V(AVDD)
NetC7_2: C22.1 C24.2 C25.2 C26.2 R32.1 R33.1 R34.1 U3.26 ; port AGND

Not connected (* = marked no-connect by the designer): P1 2

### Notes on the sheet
- MCU
- 1608
- (near R31) 1608
- (near C26) 1608
- (near C22) 1608
- (near R38) 1608
- (near R27) 1608
- (near R28) 1608
- (near R37) 1608
- (near C27) 1608
- (near C28) 1608
- (near P1) Connector to Accessory Board

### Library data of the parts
C22 = C: as C4 on sheet 1
C23 = C#1: as C15 on sheet 3
C24-C26 = C#1: PARTNAME: 10NF_K; OriginalSymbolOrigin: (2540,7620); CaptureCellPackProp: C##1
C27 = CAP_CC_1: OriginalSymbolOrigin: (0,0); SAVECOUNT: 1; UPDATETIME: 14:48:25; UPDATEUSER: d5009410; INSTANCENAME: INS257720
C28 = CAP_CC_1: OriginalSymbolOrigin: (0,0); SAVECOUNT: 1; UPDATETIME: 14:48:25; UPDATEUSER: d5009410; INSTANCENAME: INS257660
P1 = HEADER_10X2A: PARTNAME: 10X2A_1-25; OriginalSymbolOrigin: (0,0); SAVEAREA0: -38178,-50023,47755,12978; SAVECOUNT: 4; UPDATETIME: 13:19:25; UPDATEUSER: t5459927; TIME: 14:48:25
R27 = R: PARTNAME: 0_K; OriginalSymbolOrigin: (5080,5080)
R28 = R#1: PARTNAME: 0_K; OriginalSymbolOrigin: (5080,5080); CaptureCellPackProp: R##1
R29 = R: PARTNAME: 51_K; OriginalSymbolOrigin: (5080,5080)
R30 R31 = R#1: PARTNAME: 51_K; OriginalSymbolOrigin: (5080,5080); CaptureCellPackProp: R##1
R32-R34 = R: PARTNAME: 0K_K; OriginalSymbolOrigin: (5080,5080)
R35-R37 = R: as R19 on sheet 3
R38 = R#1: PARTNAME: 10K_K; OriginalSymbolOrigin: (5080,5080); CaptureCellPackProp: R##1
U3 = ETOOLMICON: OriginalSymbolOrigin: (-10160,7620); SAVEAREA0: -22560,-61894,97211,9095; SAVECOUNT: 11; UPDATETIME: 15:48:18; UPDATEUSER: t5459927; TIME: 14:48:25
U?#5 = WAKU_DEF100: OriginalSymbolOrigin: (10160,284480); SAVECOUNT: 4; UPDATETIME: 15:07:21; UPDATEUSER: t5459927; TIME: 14:30:25; SAVEAREA0: 198008,-65938,436964,90161; PLOTTIME: HH:MM

## Sheet 6.SchDoc
size 420 x 297 mm
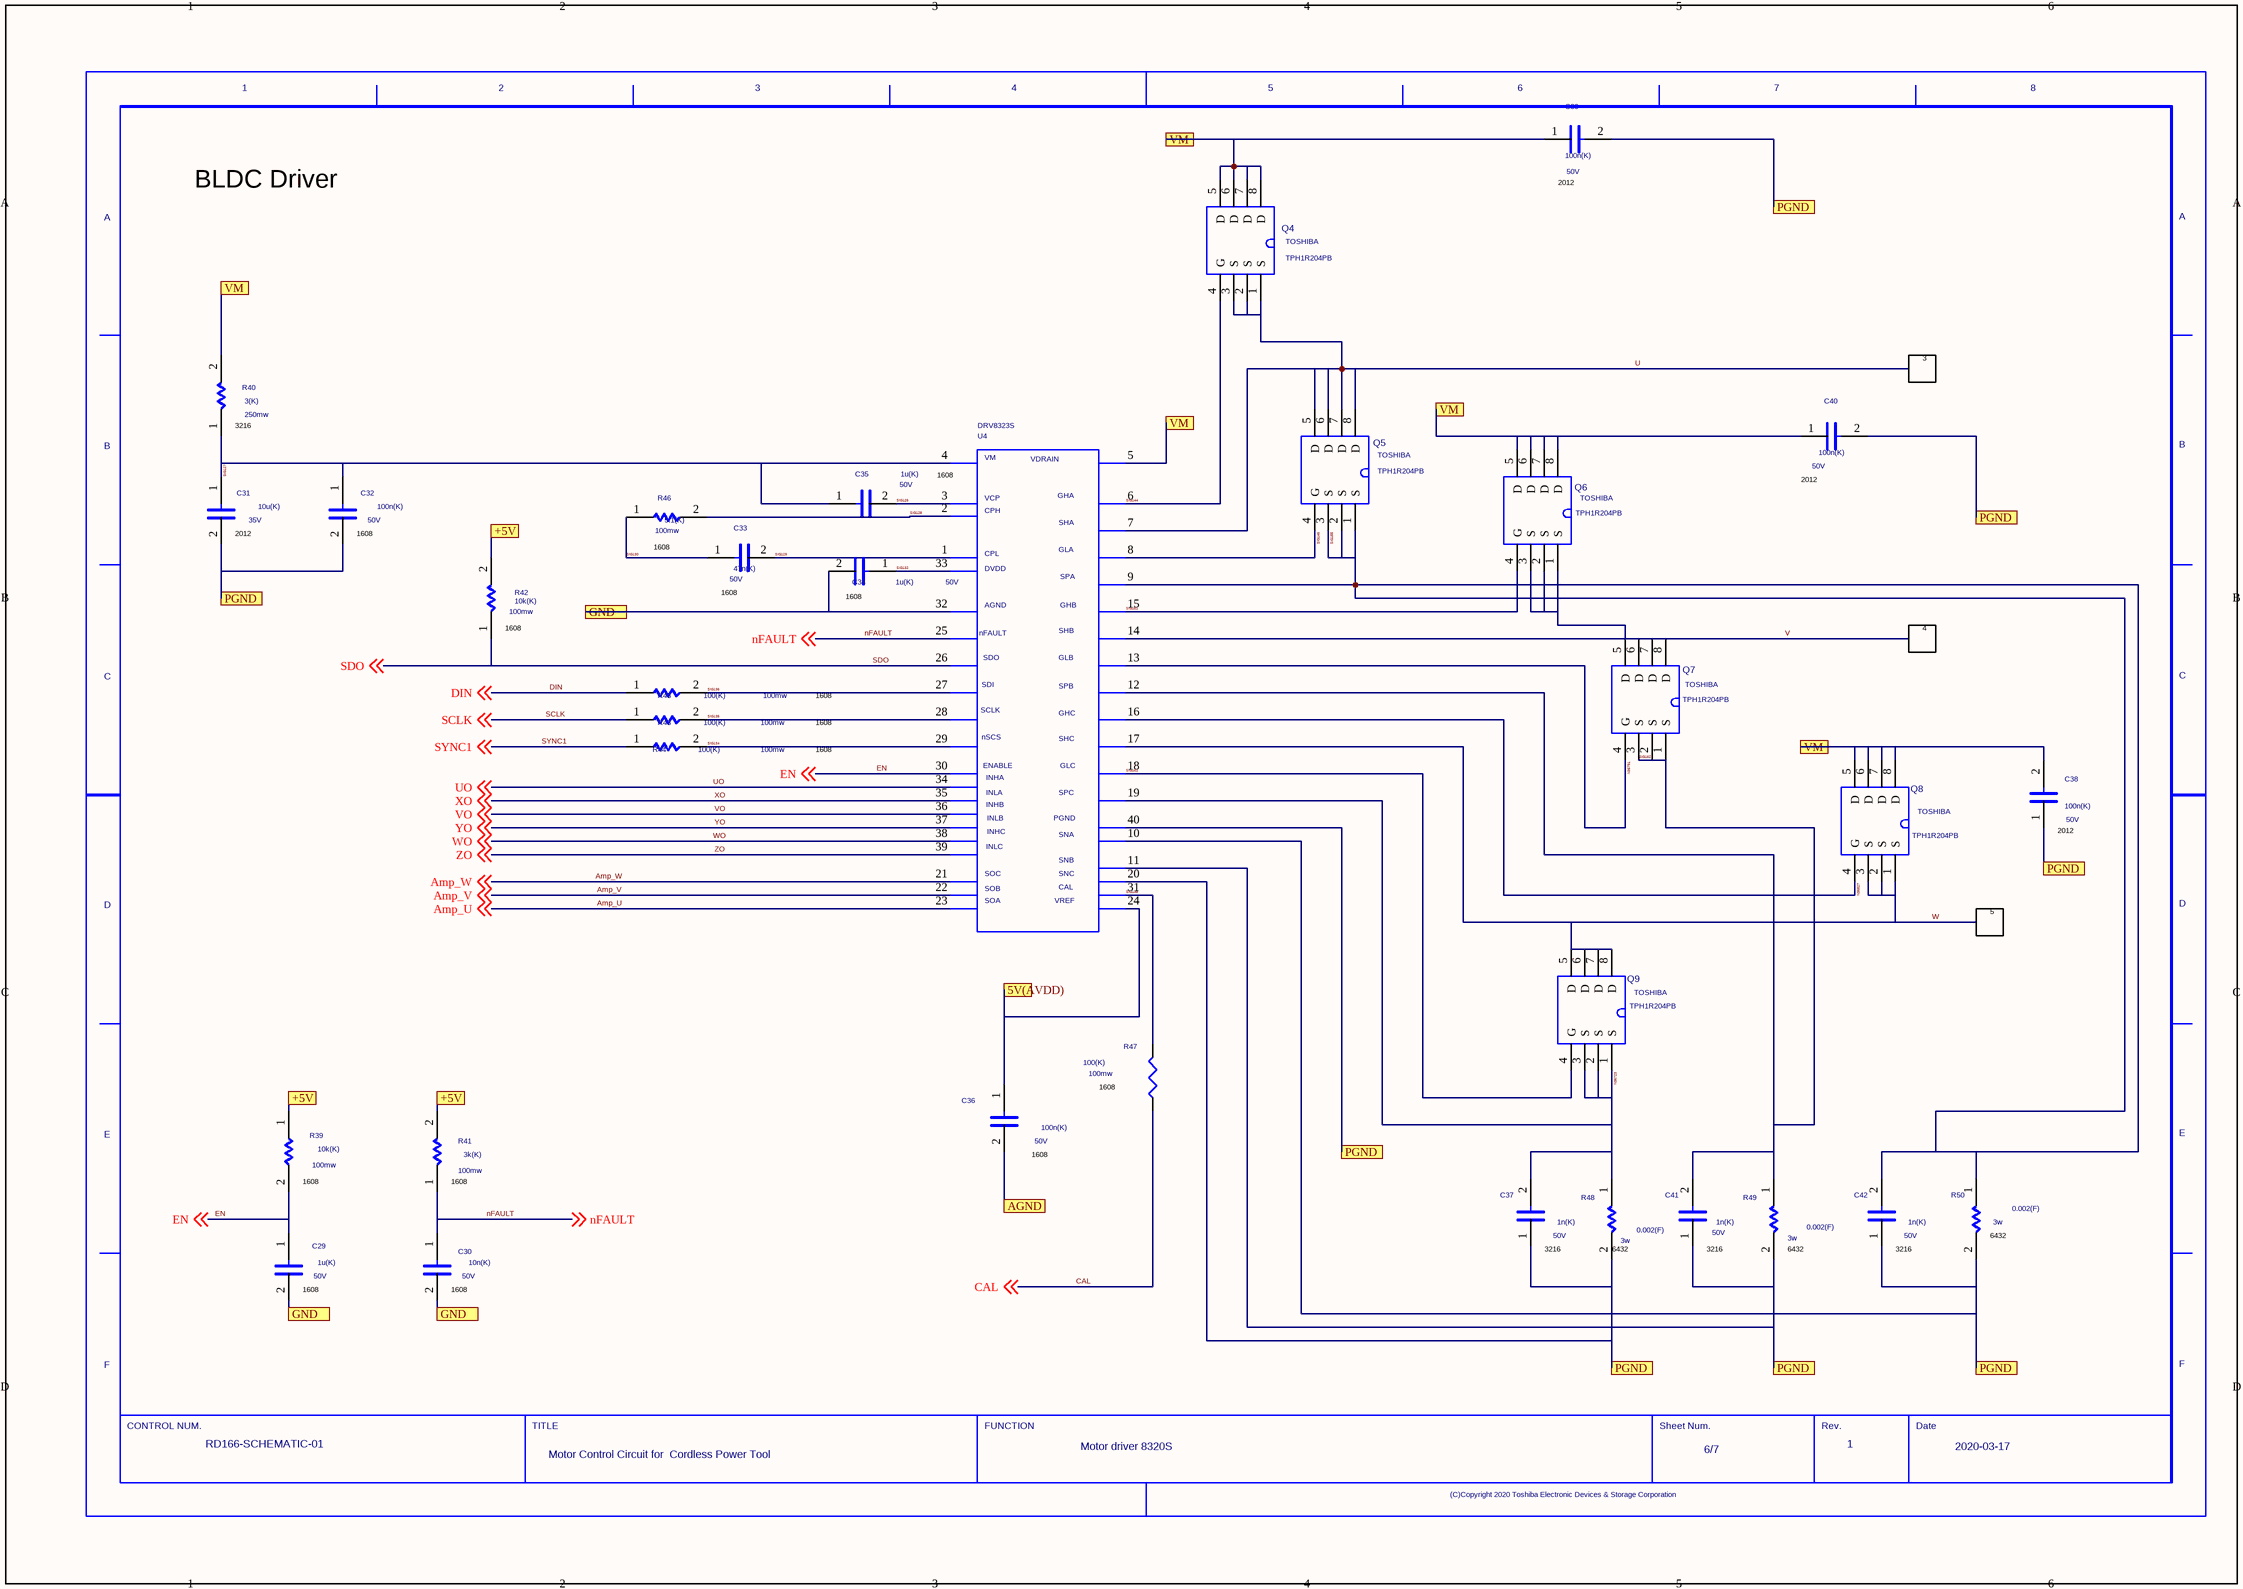
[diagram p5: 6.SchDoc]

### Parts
(Parts that share a designator on the sheet are numbered #1, #2 ... from top to bottom, then left to right.)
C29  VAL1: 1u(K)  VAL2: 50V  (hidden comment: C)
C30  VAL1: 10n(K)  VAL2: 50V  (hidden comment: C)
C31  VAL1: 10u(K)  VAL2: 35V  (hidden comment: C)
C32  VAL1: 100n(K)  VAL2: 50V  (hidden comment: C)
C33  VAL1: 47n(K)  VAL2: 50V  (hidden comment: C)
C34  VAL1: 1u(K)  VAL2: 50V  (hidden comment: C)
C35  VAL1: 1u(K)  VAL2: 50V  (hidden comment: C)
C36  VAL1: 100n(K)  VAL2: 50V  (hidden comment: C)
C37  VAL1: 1n(K)  VAL2: 50V  (hidden comment: C)
C38  VAL1: 100n(K)  VAL2: 50V  (hidden comment: C)
C39  VAL1: 100n(K)  VAL2: 50V  (hidden comment: C)
C40  VAL1: 100n(K)  VAL2: 50V  (hidden comment: C)
C41  VAL1: 1n(K)  VAL2: 50V  (hidden comment: C)
C42  VAL1: 1n(K)  VAL2: 50V  (hidden comment: C)
Q4  USERCOMPTEXT3: TOSHIBA  [SO-8]  (hidden comment: TPH1R204PB)
Q5  USERCOMPTEXT3: TOSHIBA  [SO-8]  (hidden comment: TPH1R204PB)
Q6  USERCOMPTEXT3: TOSHIBA  [SO-8]  (hidden comment: TPH1R204PB)
Q7  USERCOMPTEXT3: TOSHIBA  [SO-8]  (hidden comment: TPH1R204PB)
Q8  USERCOMPTEXT3: TOSHIBA  [SO-8]  (hidden comment: TPH1R204PB)
Q9  USERCOMPTEXT3: TOSHIBA  [SO-8]  (hidden comment: TPH1R204PB)
R39  VAL1: 10k(K)  VAL2: 100mw  (hidden comment: R)
R40  VAL1: 3(K)  VAL2: 250mw  (hidden comment: R)
R41  VAL1: 3k(K)  VAL2: 100mw  (hidden comment: R)
R42  VAL1: 10k(K)  VAL2: 100mw  (hidden comment: R)
R43  VAL1: 100(K)  VAL2: 100mw  (hidden comment: R)
R44  VAL1: 100(K)  VAL2: 100mw  (hidden comment: R)
R45  VAL1: 100(K)  VAL2: 100mw  (hidden comment: R)
R46  VAL1: 5.1(K)  VAL2: 100mw  (hidden comment: R)
R47  VAL1: 100(K)  VAL2: 100mw  [0603-1]  (hidden comment: 100_K)
R48  VAL1: 0.002(F)  VAL2: 3w  (hidden comment: R)
R49  VAL1: 0.002(F)  VAL2: 3w  (hidden comment: R)
R50  VAL1: 0.002(F)  VAL2: 3w  (hidden comment: R)
U4  DRV8323S
U?#6  DATE: 2020-03-17  REVISION: 1  SHEETNUMBER: 6/7  FUNCTION: Motor driver 8320S  TITLE: Motor Control Circuit for / Cordless Power Tool  DRAWINGNUMBER: RD166-SCHEMATIC-01  (hidden comment: WAKU_DEF100)

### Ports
5V(AVDD), +5V, AGND, GND, PGND, VM

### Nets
Amp_U: U4.23 ; off-sheet Amp_U
Amp_V: U4.22 ; off-sheet Amp_V
Amp_W: U4.21 ; off-sheet Amp_W
CAL: R47.1 ; off-sheet CAL
DIN: R45.1 ; off-sheet DIN
EN: C29.1 R39.2 U4.30 ; off-sheet EN
N36723: C37.2 Q9.1(S) Q9.2(S) Q9.3(S) R48.1 U4.19
N36791: Q7.4(G) U4.13
N36827: Q8.4(G) U4.16
nFAULT: C30.1 R41.1 U4.25 ; off-sheet nFAULT
SCLK: R43.1 ; off-sheet SCLK
SDO: R42.1 U4.26 ; off-sheet SDO
SIG29: C29.2 C30.2 C34.2 U4.32 ; port GND
SIG42: R39.1 R41.2 R42.2 ; port +5V
SIG126: C35.2 U4.3
SIG127: C31.1 C32.1 C35.1 R40.1 U4.4
SIG128: R46.2 U4.2
SIG129: C33.2 U4.1
SIG130: C33.1 R46.1
SIG132: C34.1 U4.33
SIG134: R44.2 U4.29
SIG135: R43.2 U4.28
SIG136: R45.2 U4.27
SIG138: R47.2 U4.31
SIG144: Q4.4(G) U4.6
SIG145: Q5.4(G) U4.8
SIG151: Q6.4(G) U4.15
SIG155: C42.2 Q5.1(S) Q5.2(S) Q5.3(S) R50.1 U4.9
SIG161: Q9.4(G) U4.18
SIG162: C41.2 Q7.1(S) Q7.2(S) Q7.3(S) R49.1 U4.12
SIG165: C31.2 C32.2 C37.1 C38.1 C39.2 C40.2 C41.1 C42.1 R48.2 R49.2 R50.2 U4.10 U4.11 U4.20 U4.40 ; port PGND
SYNC1: R44.1 ; off-sheet SYNC1
U: Q4.1(S) Q4.2(S) Q4.3(S) Q5.5(D) Q5.6(D) Q5.7(D) Q5.8(D) U4.7
UO: U4.34 ; off-sheet UO
V: Q6.1(S) Q6.2(S) Q6.3(S) Q7.5(D) Q7.6(D) Q7.7(D) Q7.8(D) U4.14
VM: C38.2 C39.1 C40.1 Q4.5(D) Q4.6(D) Q4.7(D) Q4.8(D) Q6.5(D) Q6.6(D) Q6.7(D) Q6.8(D) Q8.5(D) Q8.6(D) Q8.7(D) Q8.8(D) R40.2 U4.5 ; port VM
VO: U4.36 ; off-sheet VO
W: Q8.1(S) Q8.2(S) Q8.3(S) Q9.5(D) Q9.6(D) Q9.7(D) Q9.8(D) U4.17
WO: U4.38 ; off-sheet WO
XO: U4.35 ; off-sheet XO
YO: U4.37 ; off-sheet YO
ZO: U4.39 ; off-sheet ZO
NetC7_1: C36.1 U4.24 ; port 5V(AVDD)
NetC7_2: C36.2 ; port AGND

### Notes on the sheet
- BLDC Driver
- (near C39) 2012
- 3
- (near R40) 3216
- (near U4) 1608
- (near C40) 2012
- (near C31) 2012
- (near C32) 1608
- (near R46) 1608
- (near C33) 1608
- (near C34) 1608
- (near R42) 1608
- 4
- 1608
- (near C38) 2012
- 5
- (near R47) 1608
- (near R39) 1608
- (near R41) 1608
- (near C36) 1608
- (near C37) 3216
- (near R48) 6432
- (near C41) 3216
- (near R49) 6432
- (near C42) 3216
- (near R50) 6432
- (near C29) 1608
- (near C30) 1608

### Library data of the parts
C29 C35 = C: PARTNAME: 1UF_K; OriginalSymbolOrigin: (2540,7620)
C30 = C: as C7 on sheet 1
C31 = C: PARTNAME: 10UF_K; OriginalSymbolOrigin: (2540,7620)
C32 C36 = C: as C4 on sheet 1
C33 = C: PARTNAME: 50V_47NF_K; OriginalSymbolOrigin: (2540,7620)
C34 = C: PARTNAME: 50V_1UF_K; OriginalSymbolOrigin: (2540,7620)
C37 C41 C42 = C#1: PARTNAME: 1NF_K; OriginalSymbolOrigin: (2540,7620); CaptureCellPackProp: C##1
C38-C40 = C#1: PARTNAME: 50V_100NF_K; OriginalSymbolOrigin: (2540,7620); CaptureCellPackProp: C##1
Q4 = TPH1R204PB: OriginalSymbolOrigin: (0,0); SAVEAREA0: -6015,-14897,18117,2795; SAVECOUNT: 1; UPDATETIME: 14:48:25; UPDATEUSER: d5009410; INSTANCENAME: INS259044
Q5 = TPH1R204PB: OriginalSymbolOrigin: (0,0); SAVEAREA0: -6015,-14897,18117,2795; SAVECOUNT: 1; UPDATETIME: 14:48:25; UPDATEUSER: d5009410; INSTANCENAME: INS259068
Q6 = TPH1R204PB: OriginalSymbolOrigin: (0,0); SAVEAREA0: -6015,-14897,18117,2795; SAVECOUNT: 1; UPDATETIME: 14:48:25; UPDATEUSER: d5009410; INSTANCENAME: INS259092
Q7 = TPH1R204PB: OriginalSymbolOrigin: (0,0); SAVEAREA0: -6015,-14897,18117,2795; SAVECOUNT: 1; UPDATETIME: 14:48:25; UPDATEUSER: d5009410; INSTANCENAME: INS259116
Q8 = TPH1R204PB: OriginalSymbolOrigin: (0,0); SAVEAREA0: -6015,-14897,18117,2795; SAVECOUNT: 1; UPDATETIME: 14:48:25; UPDATEUSER: d5009410; INSTANCENAME: INS259140
Q9 = TPH1R204PB: OriginalSymbolOrigin: (0,0); SAVEAREA0: -6015,-14897,18117,2795; SAVECOUNT: 1; UPDATETIME: 14:48:25; UPDATEUSER: d5009410; INSTANCENAME: INS259164
R39 = R: as R19 on sheet 3
R40 = R#1: PARTNAME: 3-0_K; OriginalSymbolOrigin: (5080,5080); CaptureCellPackProp: R##1
R41 = R#1: PARTNAME: 3K_K; OriginalSymbolOrigin: (5080,5080); CaptureCellPackProp: R##1
R42 = R#1: as R38 on sheet 5
R43-R45 = R: PARTNAME: 100_K; OriginalSymbolOrigin: (5080,5080)
R46 = R: PARTNAME: 5-1_K; OriginalSymbolOrigin: (5080,5080)
R47 = RES_SMD__2#1: OriginalSymbolOrigin: (2552,2560); SAVEAREA0: -3866,-5393,16243,5158; SAVECOUNT: 2; UPDATETIME: 14:48:25; UPDATEUSER: d5009410; INSTANCENAME: INS259248; CaptureCellPackProp: RES_SMD__2##1
R48-R50 = R: PARTNAME: R002_F; OriginalSymbolOrigin: (5080,5080)
U4 = DRV8323S: OriginalSymbolOrigin: (-7620,0); SAVEAREA0: -72294,-50031,83425,15115; SAVECOUNT: 5; UPDATETIME: 15:09:32; UPDATEUSER: t5459927; TIME: 14:48:25
U?#6 = WAKU_DEF100: OriginalSymbolOrigin: (10160,284480); SAVECOUNT: 4; UPDATETIME: 15:04:57; UPDATEUSER: t5459927; TIME: 14:30:25; SAVEAREA0: 198008,-65938,436964,90161; PLOTTIME: HH:MM

## Sheet 7.SchDoc
size 420 x 297 mm
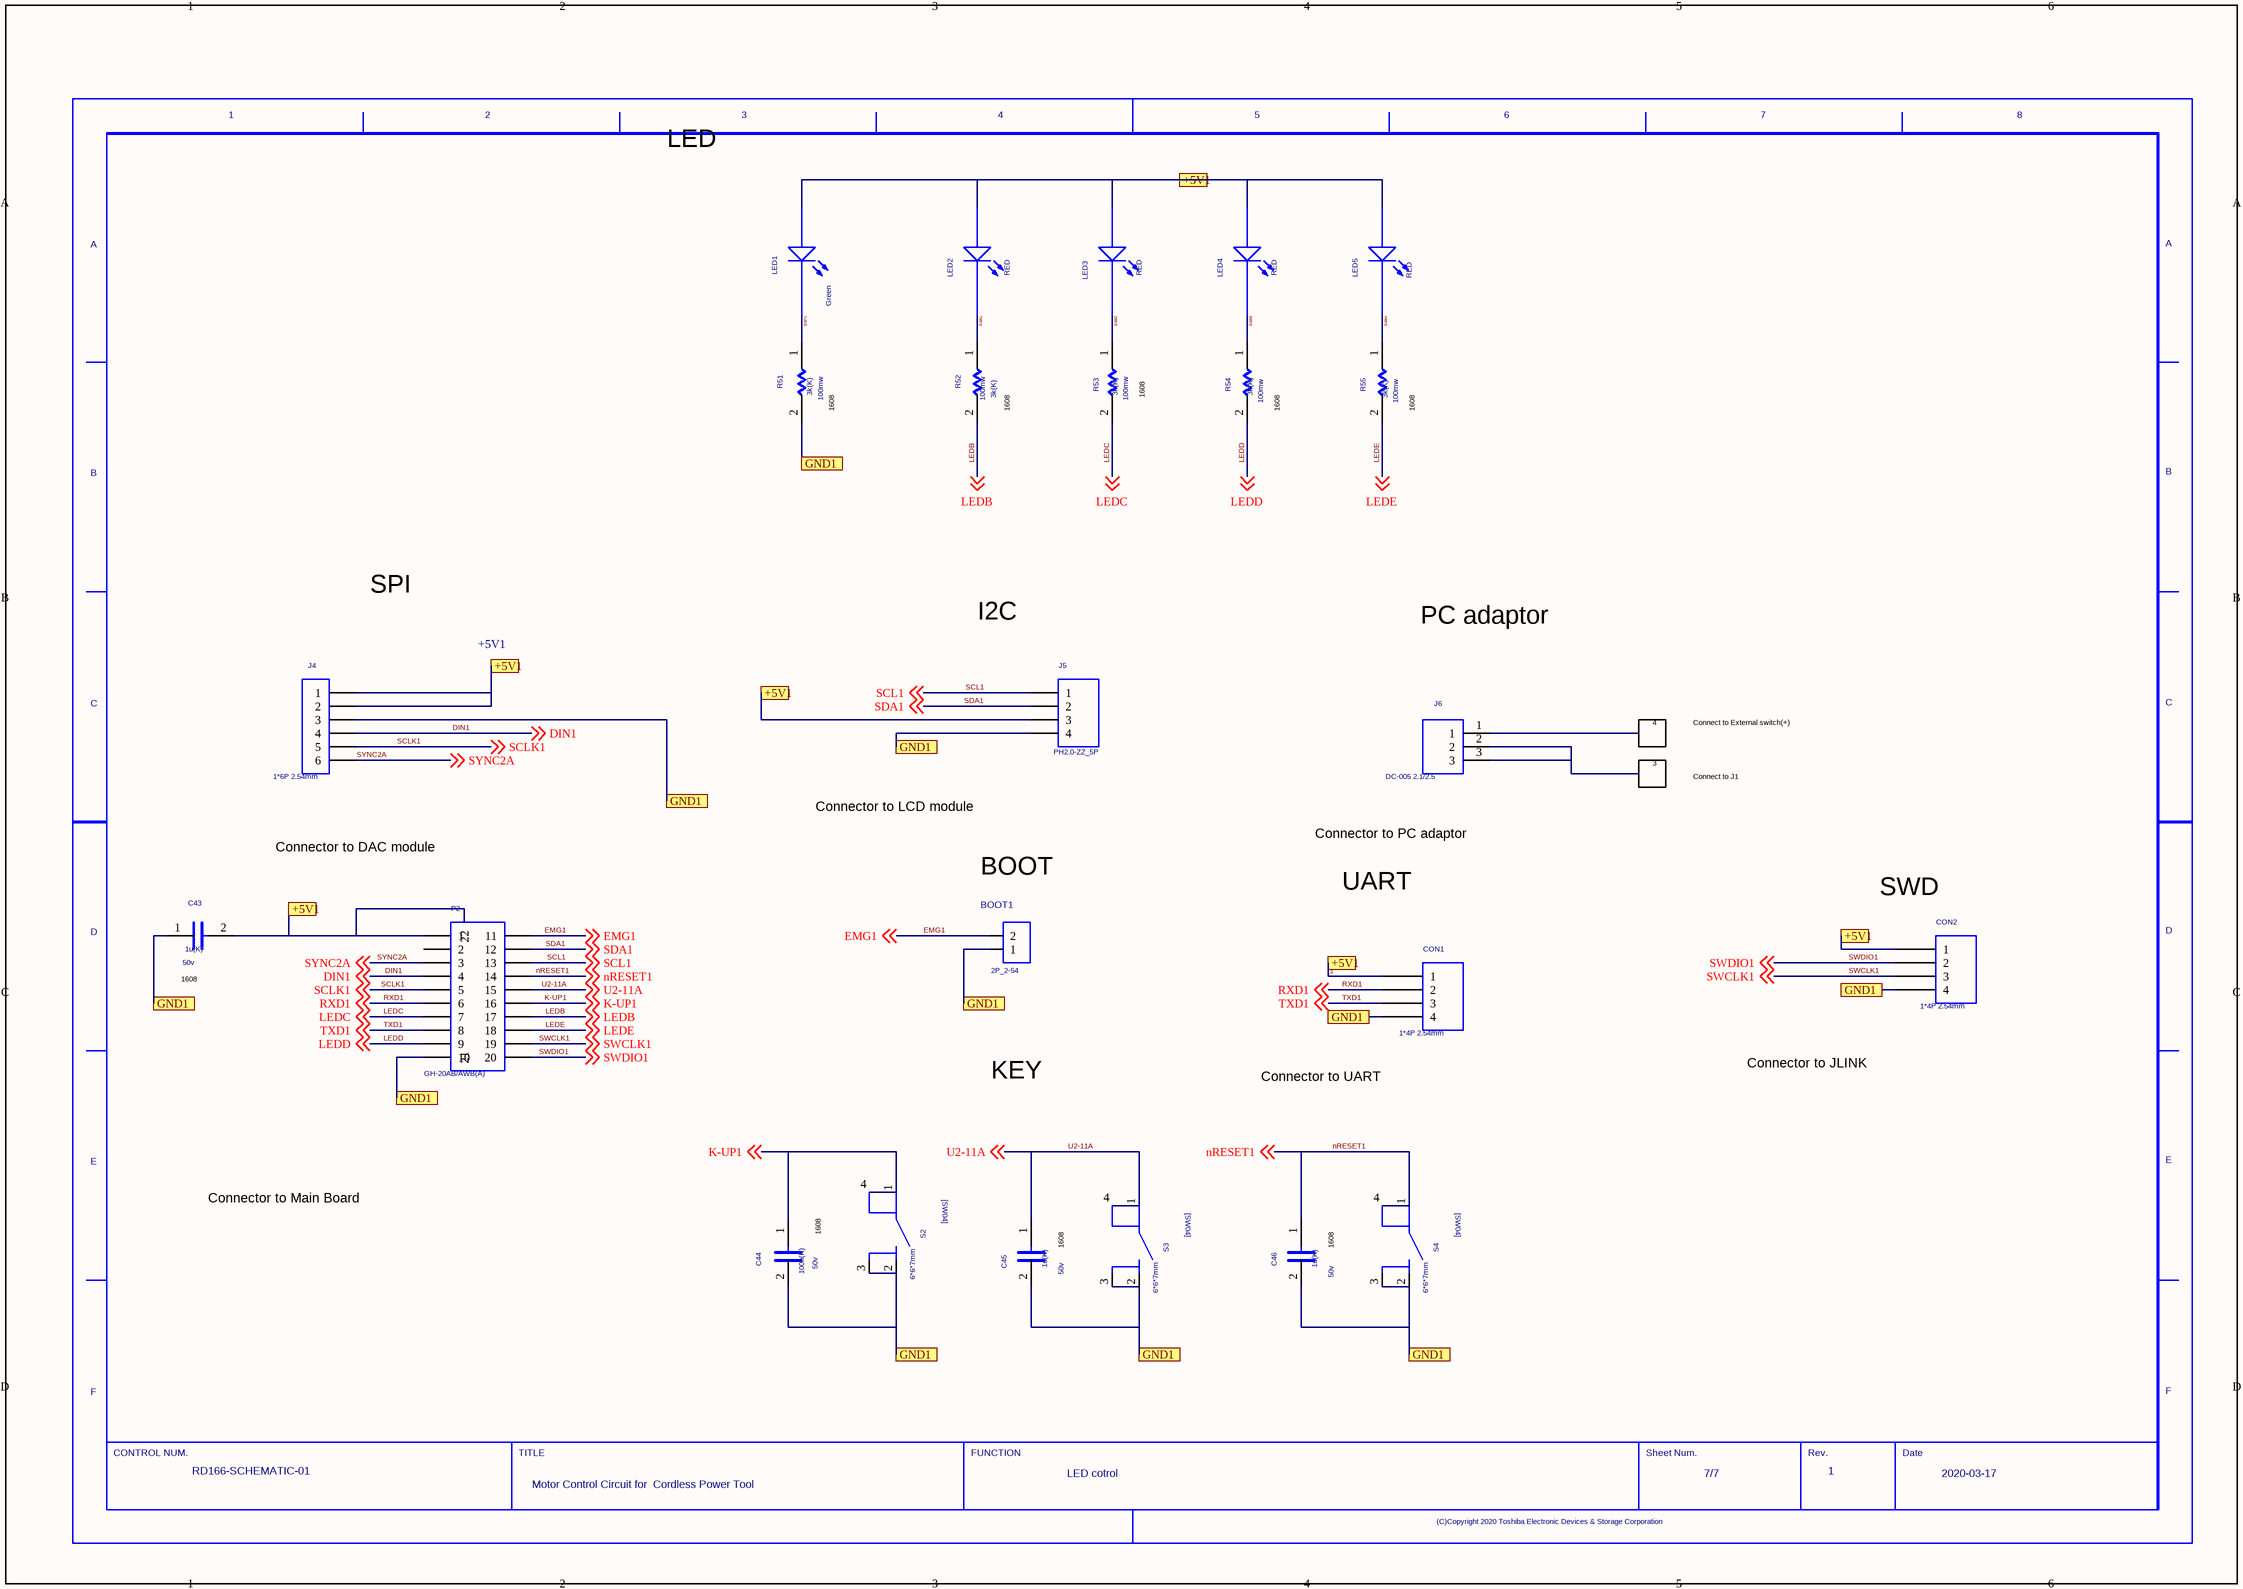
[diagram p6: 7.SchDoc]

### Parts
(Parts that share a designator on the sheet are numbered #1, #2 ... from top to bottom, then left to right.)
BOOT1  2P_2-54  [HDR1X2]
C43  VAL1: 1u(K)  VAL2: 50v  (hidden comment: C)
C44  VAL1: 100n(K)  VAL2: 50v  (hidden comment: C)
C45  VAL1: 1u(K)  VAL2: 50v  (hidden comment: C)
C46  VAL1: 1u(K)  VAL2: 50v  (hidden comment: C)
CON1  VAL3: 1*4P 2.54mm  (hidden comment: CON4)
CON2  VAL3: 1*4P 2.54mm  (hidden comment: CON4)
J4  VAL3: 1*6P 2.54mm  (hidden comment: CON6)
J5  VAL3: PH2.0-ZZ_5P  (hidden comment: HEADER_4)
J6  VAL3: DC-005 2.1/2.5  (hidden comment: CON3)
LED1  VAL3: Green  (hidden comment: LED2_2)
LED2  VAL3: RED  (hidden comment: LED2_2)
LED3  VAL3: RED  (hidden comment: LED2_2)
LED4  VAL3: RED  (hidden comment: LED2_2)
LED5  VAL3: RED  (hidden comment: LED2_2)
P2  VAL3: GH-20AB/AWB(A)  (hidden comment: HEADER_10X2A)
R51  VAL1: 3k(K)  VAL2: 100mw  (hidden comment: R)
R52  VAL1: 3k(K)  VAL2: 100mw  (hidden comment: R)
R53  VAL1: 3k(K)  VAL2: 100mw  (hidden comment: R)
R54  VAL1: 3k(K)  VAL2: 100mw  (hidden comment: R)
R55  VAL1: 3k(K)  VAL2: 100mw  (hidden comment: R)
S2  VAL3: 6*6*7mm  (hidden comment: SW04)
S3  VAL3: 6*6*7mm  (hidden comment: SW04)
S4  VAL3: 6*6*7mm  (hidden comment: SW04)
U?#7  DATE: 2020-03-17  DRAWINGNUMBER: RD166-SCHEMATIC-01  TITLE: Motor Control Circuit for / Cordless Power Tool  FUNCTION: LED cotrol  SHEETNUMBER: 7/7  REVISION: 1  (hidden comment: WAKU_DEF100)

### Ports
+5V1, GND1

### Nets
19VDC: J6.1
DIN1: J4.4 P2.4 ; off-sheet DIN1
EMG1: BOOT1.2 P2.11 ; off-sheet EMG1
K-UP1: C44.1 P2.16 S2.1 S2.4 ; off-sheet K-UP1
LEDB: P2.17 R52.2 ; off-sheet LEDB
LEDC: P2.7 R53.2 ; off-sheet LEDC
LEDD: P2.9 R54.2 ; off-sheet LEDD
LEDE: P2.18 R55.2 ; off-sheet LEDE
nRESET1: C46.1 P2.14 S4.1 S4.4 ; off-sheet nRESET1
PGND1: J6.2 J6.3
RXD1: CON1.2 P2.6 ; off-sheet RXD1
SCL1: J5.1 P2.13 ; off-sheet SCL1
SCLK1: J4.5 P2.5 ; off-sheet SCLK1
SDA1: J5.2 P2.12 ; off-sheet SDA1
SIG61: LED2.2 R52.1
SIG62: LED3.2 R53.1
SIG63: LED4.2 R54.1
SIG64: LED5.2 R55.1
SIG71: LED1.2 R51.1
SIG86: C43.2 CON1.1 CON2.1 J4.1 J4.2 J5.3 LED1.1 LED2.1 LED3.1 LED4.1 LED5.1 P2.1 P2.22 ; port +5V1
SWCLK1: CON2.3 P2.19 ; off-sheet SWCLK1
SWDIO1: CON2.2 P2.20 ; off-sheet SWDIO1
SYNC2A: J4.6 P2.3 ; off-sheet SYNC2A
TXD1: CON1.3 P2.8 ; off-sheet TXD1
U2-11A: C45.1 P2.15 S3.1 S3.4 ; off-sheet U2-11A
NetBOOT1_1: BOOT1.1 C43.1 C44.2 C45.2 C46.2 CON1.4 CON2.4 J4.3 J5.4 P2.10 R51.2 S2.2 S2.3 S3.2 S3.3 S4.2 S4.3 ; port GND1

Not connected (* = marked no-connect by the designer): P2 2 21

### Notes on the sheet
- LED
- (near R53) 1608
- (near R51) 1608
- (near R52) 1608
- (near R54) 1608
- (near R55) 1608
- SPI
- +5V1
- I2C
- PC adaptor
- 4
- Connect to External switch(+)
- 3
- Connect to J1
- Connector to DAC module
- Connector to LCD module
- Connector to PC adaptor
- BOOT
- UART
- (near CON2) SWD
- (near C43) 1608
- Connector to JLINK
- KEY
- Connector to UART
- Connector to Main Board
- 1608
- (near C45) 1608
- (near C46) 1608

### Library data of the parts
BOOT1 = HEADER_1X2: OriginalSymbolOrigin: (0,0); SAVEAREA0: -1901,-7788,9280,409; SAVECOUNT: 1; UPDATETIME: 14:48:25; UPDATEUSER: d5009410; INSTANCENAME: INS260186
C43 = C#1: as C14 on sheet 3
C44 = C: PARTNAME: 100NF_K_2; OriginalSymbolOrigin: (2540,7620)
C45 C46 = C: as C29 on sheet 6
CON1 CON2 = CON4: PARTNAME: 4P_2-54; OriginalSymbolOrigin: (0,0); SAVEAREA0: -9538,-12954,9100,710; SAVECOUNT: 2; UPDATETIME: 11:51:19; UPDATEUSER: t5459927; TIME: 14:48:25
J4 = CON6: PARTNAME: 6P_2-54; OriginalSymbolOrigin: (0,0); SAVEAREA0: -13352,-18135,12740,994; SAVECOUNT: 2; UPDATETIME: 11:51:01; UPDATEUSER: t5459927; TIME: 14:48:25
J5 = HEADER_4: PARTNAME: 4P_2-0; OriginalSymbolOrigin: (0,0); SAVEAREA0: -8253,-12954,10385,710; SAVECOUNT: 2; UPDATETIME: 17:19:04; UPDATEUSER: t5459927; TIME: 14:48:25
J6 = CON3: PARTNAME: PER-5-L; OriginalSymbolOrigin: (0,0); SAVEAREA0: -6361,-10384,8548,546; SAVECOUNT: 2; UPDATETIME: 16:17:55; UPDATEUSER: t5459927; TIME: 14:48:25
LED1 = LED2_2: PARTNAME: 0603_Green; OriginalSymbolOrigin: (-10160,-3); SAVEAREA0: -21848,-22501,27655,13791; SAVECOUNT: 3; UPDATETIME: 08:39:51; UPDATEUSER: t5459927; TIME: 14:48:25
LED2-LED5 = LED2_2: PARTNAME: 0603_RED; OriginalSymbolOrigin: (-10160,-3); SAVEAREA0: -21848,-22501,27655,13791; SAVECOUNT: 3; UPDATETIME: 08:39:51; UPDATEUSER: t5459927; TIME: 14:48:25
P2 = HEADER_10X2A: PARTNAME: 10X2A_1-25_2; OriginalSymbolOrigin: (0,0); SAVEAREA0: -38178,-50023,47755,12978; SAVECOUNT: 4; UPDATETIME: 13:19:25; UPDATEUSER: t5459927; TIME: 14:48:25
R51-R55 = R: PARTNAME: 3K_K; OriginalSymbolOrigin: (5080,5080)
S2 = SW04: PARTNAME: KEY1; OriginalSymbolOrigin: (0,10160); SAVECOUNT: 1; UPDATETIME: 18:00:32; UPDATEUSER: 19870035; SAVEAREA0: -7718,-213,22668,18275
S3 = SW04: PARTNAME: KEY2; OriginalSymbolOrigin: (0,10160); SAVECOUNT: 1; UPDATETIME: 18:00:32; UPDATEUSER: 19870035; SAVEAREA0: -7718,-213,22668,18275
S4 = SW04: PARTNAME: RESET; OriginalSymbolOrigin: (0,10160); SAVECOUNT: 1; UPDATETIME: 18:00:32; UPDATEUSER: 19870035; SAVEAREA0: -7718,-213,22668,18275
U?#7 = WAKU_DEF100: OriginalSymbolOrigin: (10160,284480); SAVECOUNT: 4; UPDATETIME: 15:05:31; UPDATEUSER: t5459927; TIME: 14:30:25; SAVEAREA0: 198008,-65938,436964,90161; PLOTTIME: HH:MM

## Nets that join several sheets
Amp_U: 3 (U1.2), 5 (R31.2), 6 (U4.23)
Amp_V: 3 (U1.6), 5 (R30.2), 6 (U4.22)
Amp_W: 3 (U2.6), 5 (R29.1), 6 (U4.21)
CAL: 5 (U3.37), 6 (R47.1)
DIN: 5 (P1.4 U3.41), 6 (R45.1)
EMG: 3 (C17.1 R23.1), 5 (P1.11 R38.2 U3.15)
FR1: 2 (C10.1 R12.2), 5 (U3.14)
Hu: 4 (C21.1 J3.2 R26.1), 5 (U3.44)
Hv: 4 (C20.1 J3.3 R25.1), 5 (U3.45)
Hw: 4 (C19.1 J3.4 R24.1), 5 (U3.46)
LED+: 1 (R3.2), 2 (SW1.7)
LED-: 1 (Q3.3), 2 (SW1.8)
NetC7_1: 1 (C7.1 C8.1 R10.2), 5 (C22.2 U3.38), 6 (C36.1 U4.24)
NetC7_2: 1 (C7.2 C8.2 R11.2), 5 (8 pins), 6 (C36.2)
nFAULT: 5 (U3.13), 6 (C30.1 R41.1 U4.25)
Pdelay: 1 (R1.2 R7.1), 5 (U3.36)
SCLK: 5 (P1.5 U3.43), 6 (R43.1)
SDO: 5 (U3.42), 6 (R42.1 U4.26)
SIG29: 1 (11 pins), 2 (7 pins), 3 (8 pins), 4 (5 pins), 5 (9 pins), 6 (C29.2 C30.2 C34.2 U4.32)
SIG42: 1 (C6.1 C9.1 IC2.3 R10.1), 2 (D3.2 R16.1 SW1.0 SW1.2), 3 (8 pins), 4 (5 pins), 5 (8 pins), 6 (R39.1 R41.2 R42.2)
SIG164: 1 (Q1.2 R2.1 R4.2), 2 (SW1.1)
SIG165: 1 (5 pins), 6 (15 pins)
SIG166: 1 (D1.2 Q1.3), 2 (R14.2)
SYNC1: 5 (U3.40), 6 (R44.1)
Tmos: 2 (C13.1 NTC1.2 R16.2), 5 (U3.35)
UO: 5 (U3.21), 6 (U4.34)
VDC_AD: 2 (C12.1 D3.1 R14.1 R15.2), 5 (U3.34)
VM: 1 (C1.1 C2.1 D2.2), 6 (17 pins)
VO: 5 (U3.19), 6 (U4.36)
Vsp: 2 (C11.1 R13.2), 5 (U3.33)
WO: 5 (U3.17), 6 (U4.38)
XO: 5 (U3.20), 6 (U4.35)
YO: 5 (U3.18), 6 (U4.37)
ZO: 5 (U3.16), 6 (U4.39)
